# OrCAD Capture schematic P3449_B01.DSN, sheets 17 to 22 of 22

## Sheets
17 0005_SODIMM connector 2_3: size Custom
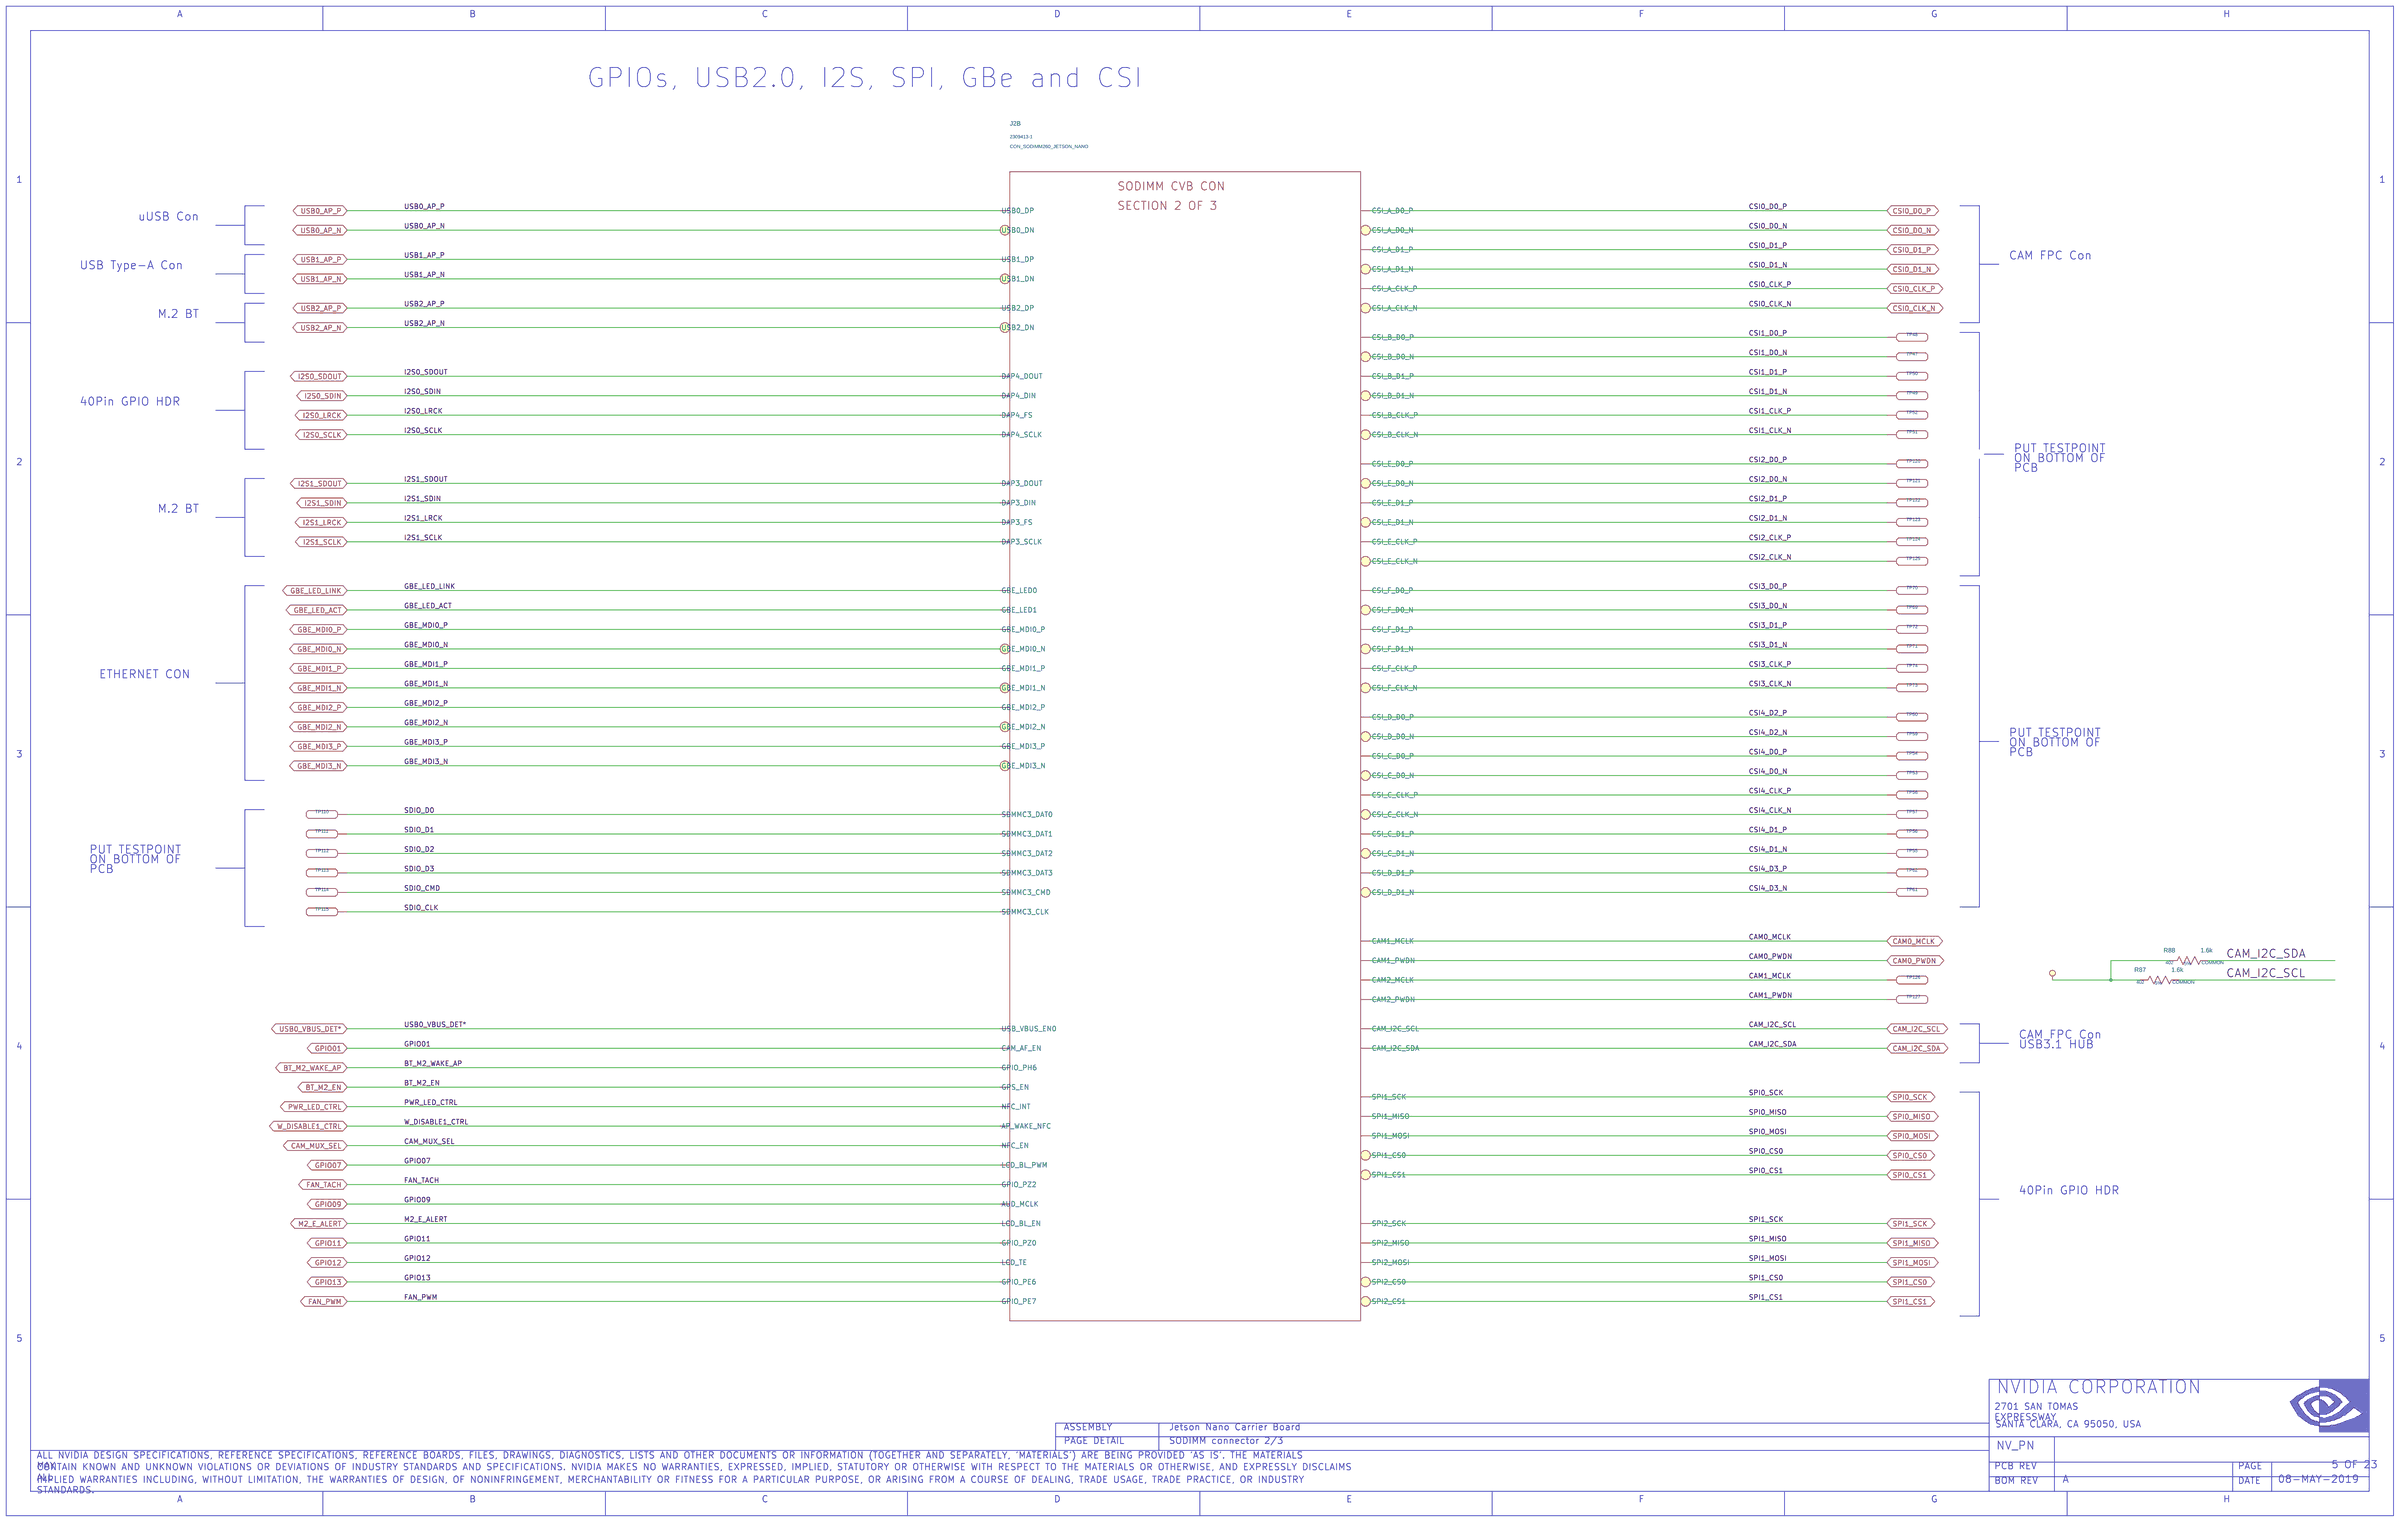
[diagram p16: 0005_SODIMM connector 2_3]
18 0004_SODIMM connector 1_3: size Custom
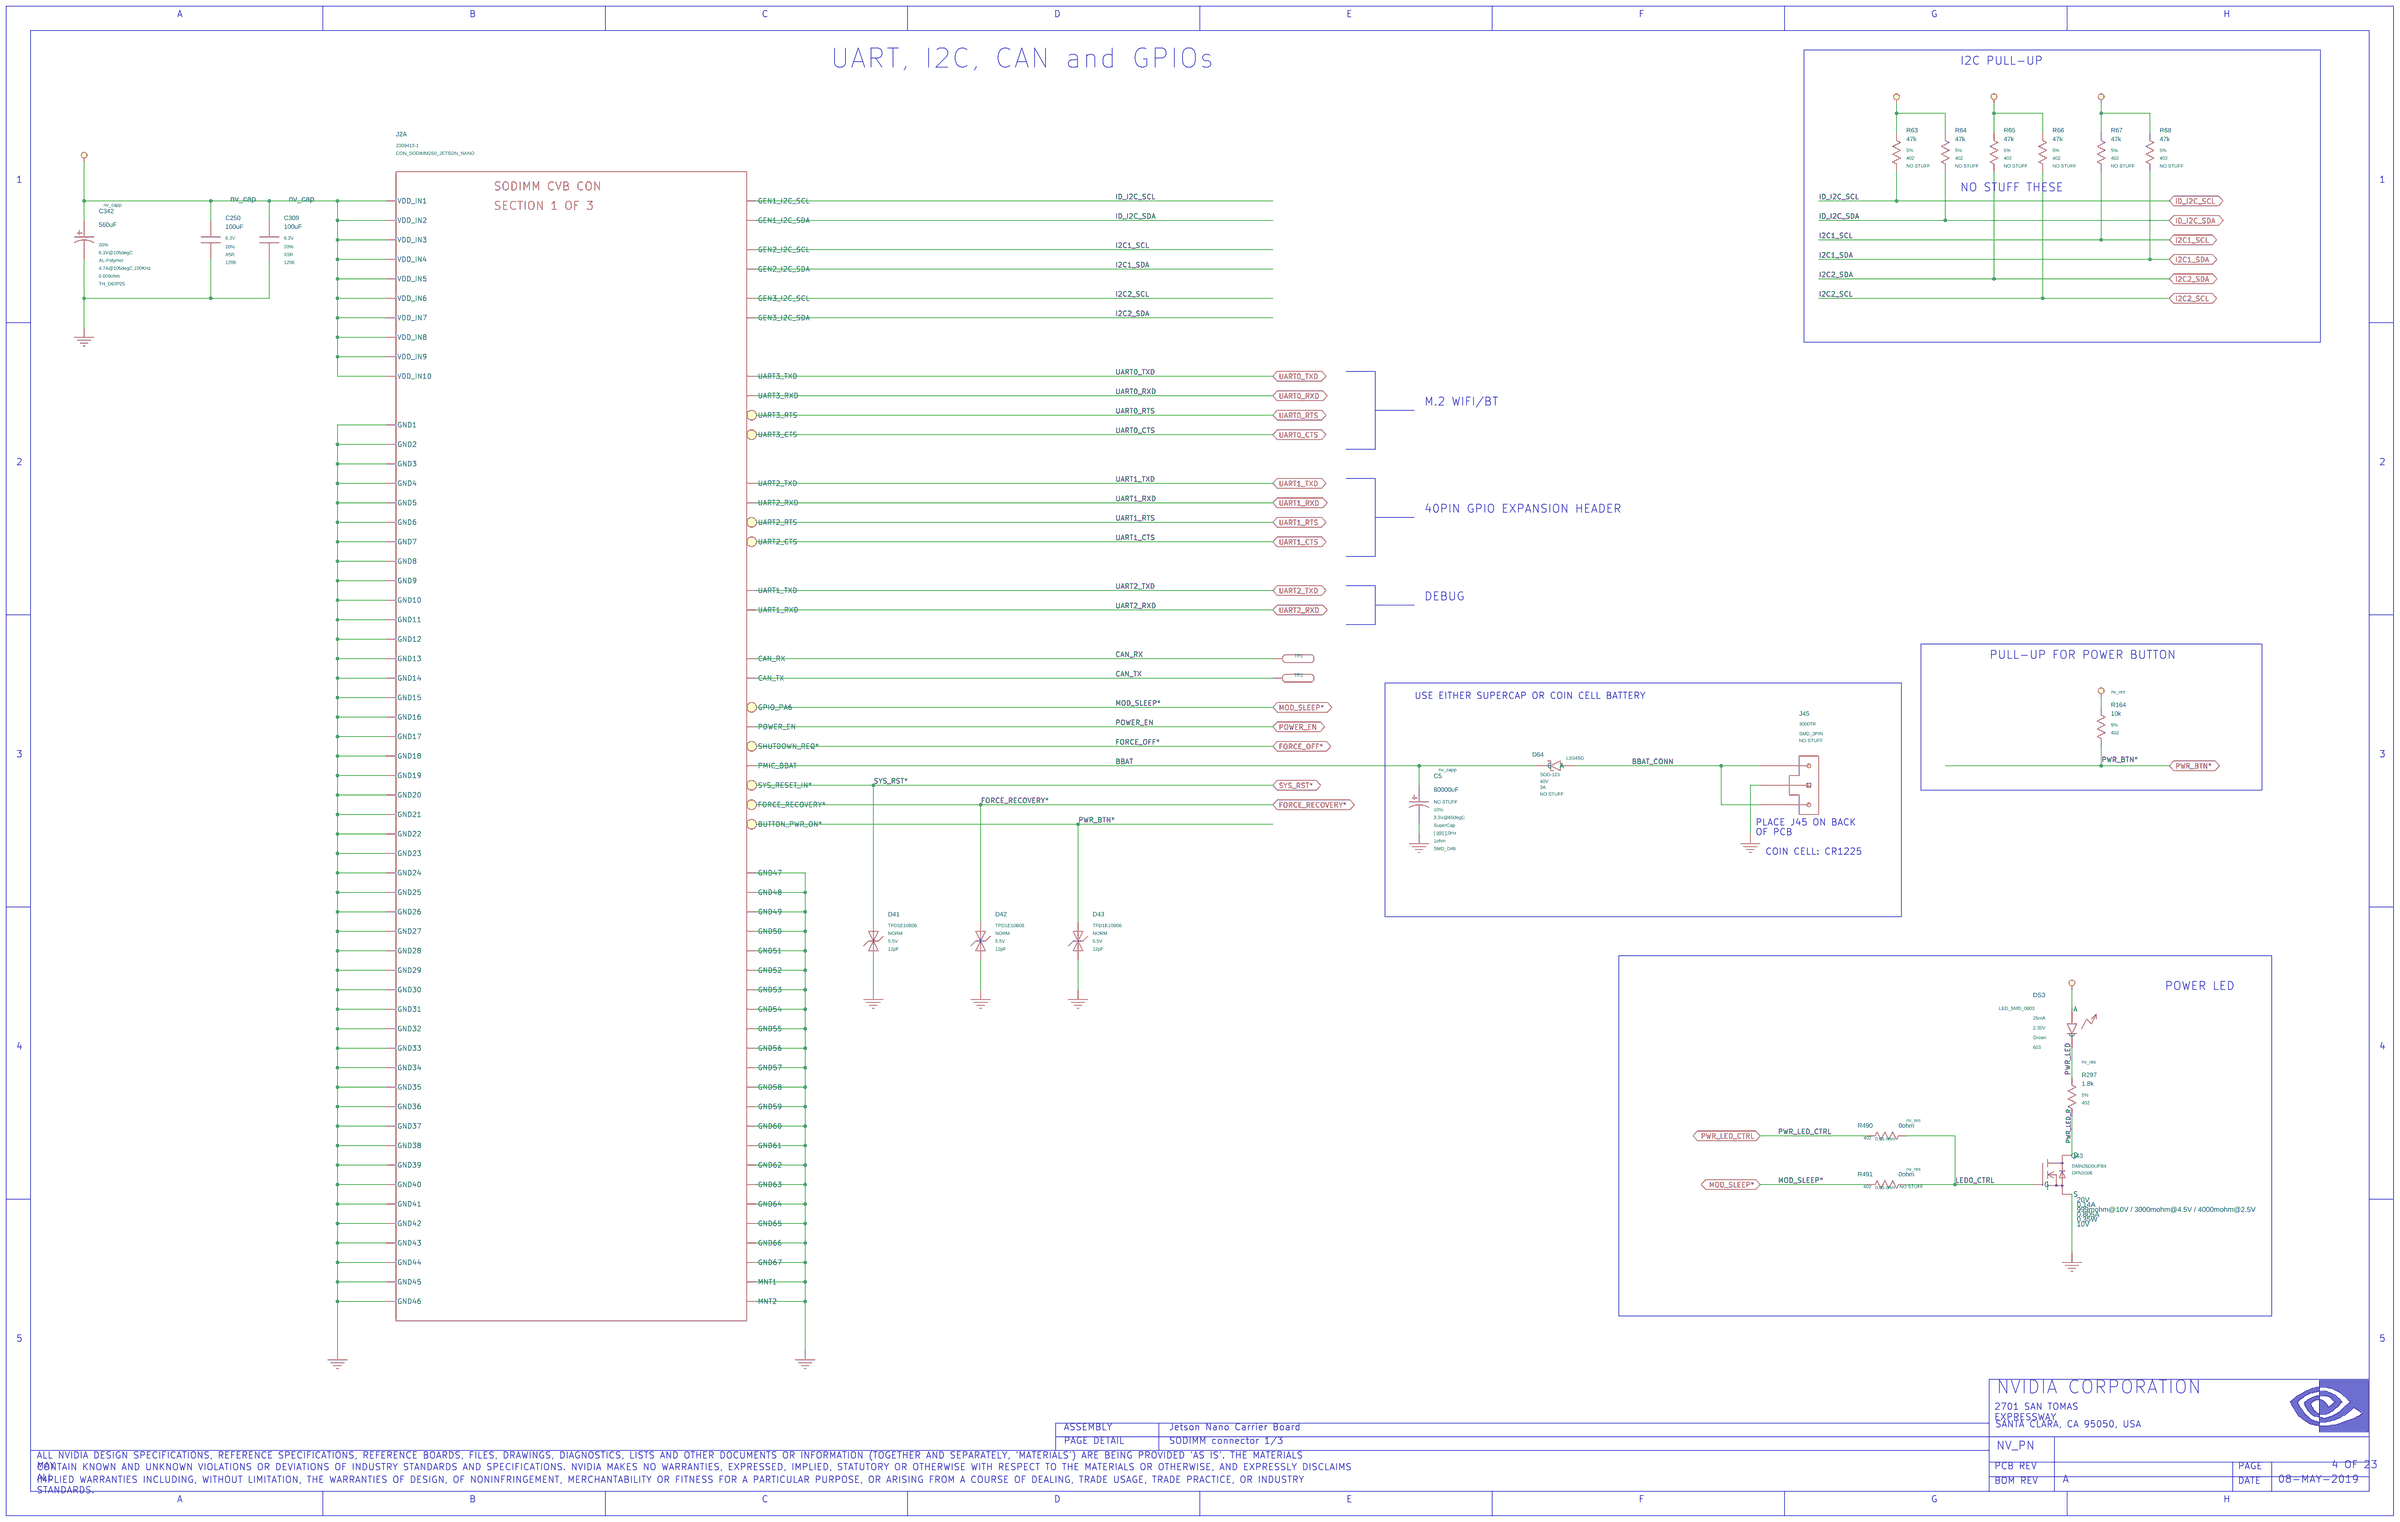
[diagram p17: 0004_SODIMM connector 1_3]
19 0003_Power Tree
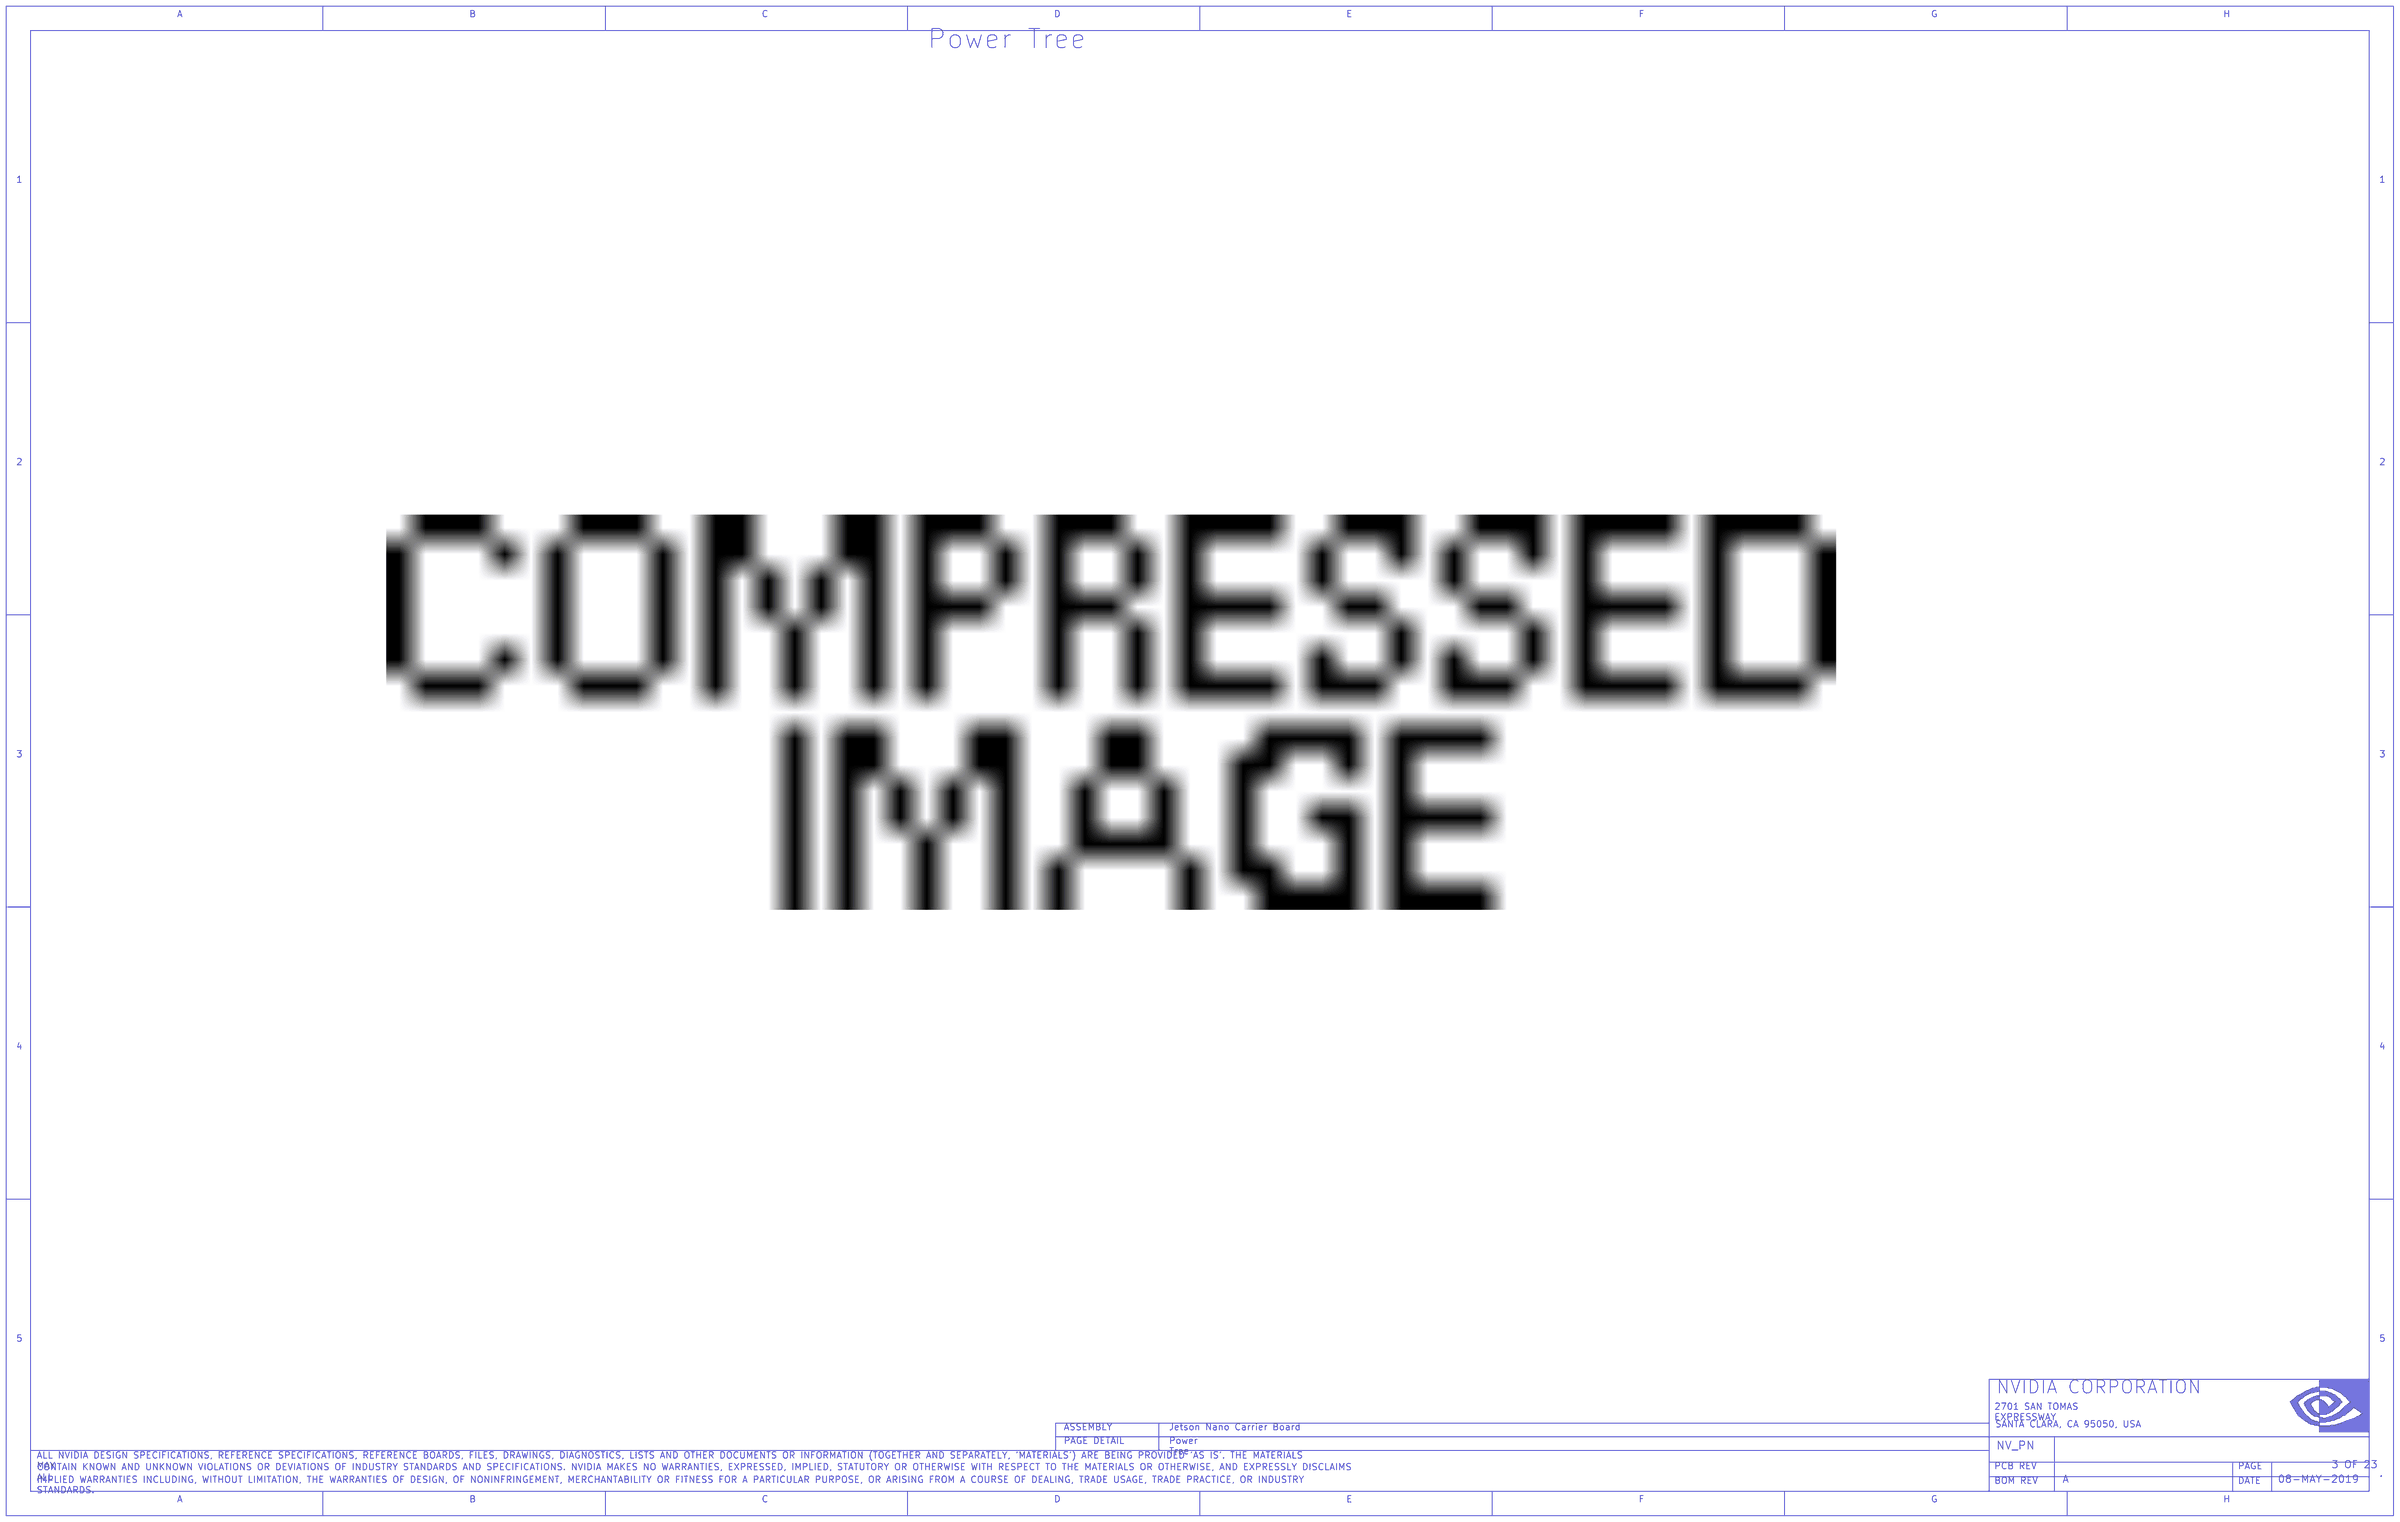
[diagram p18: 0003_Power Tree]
20 0002_Blank Page
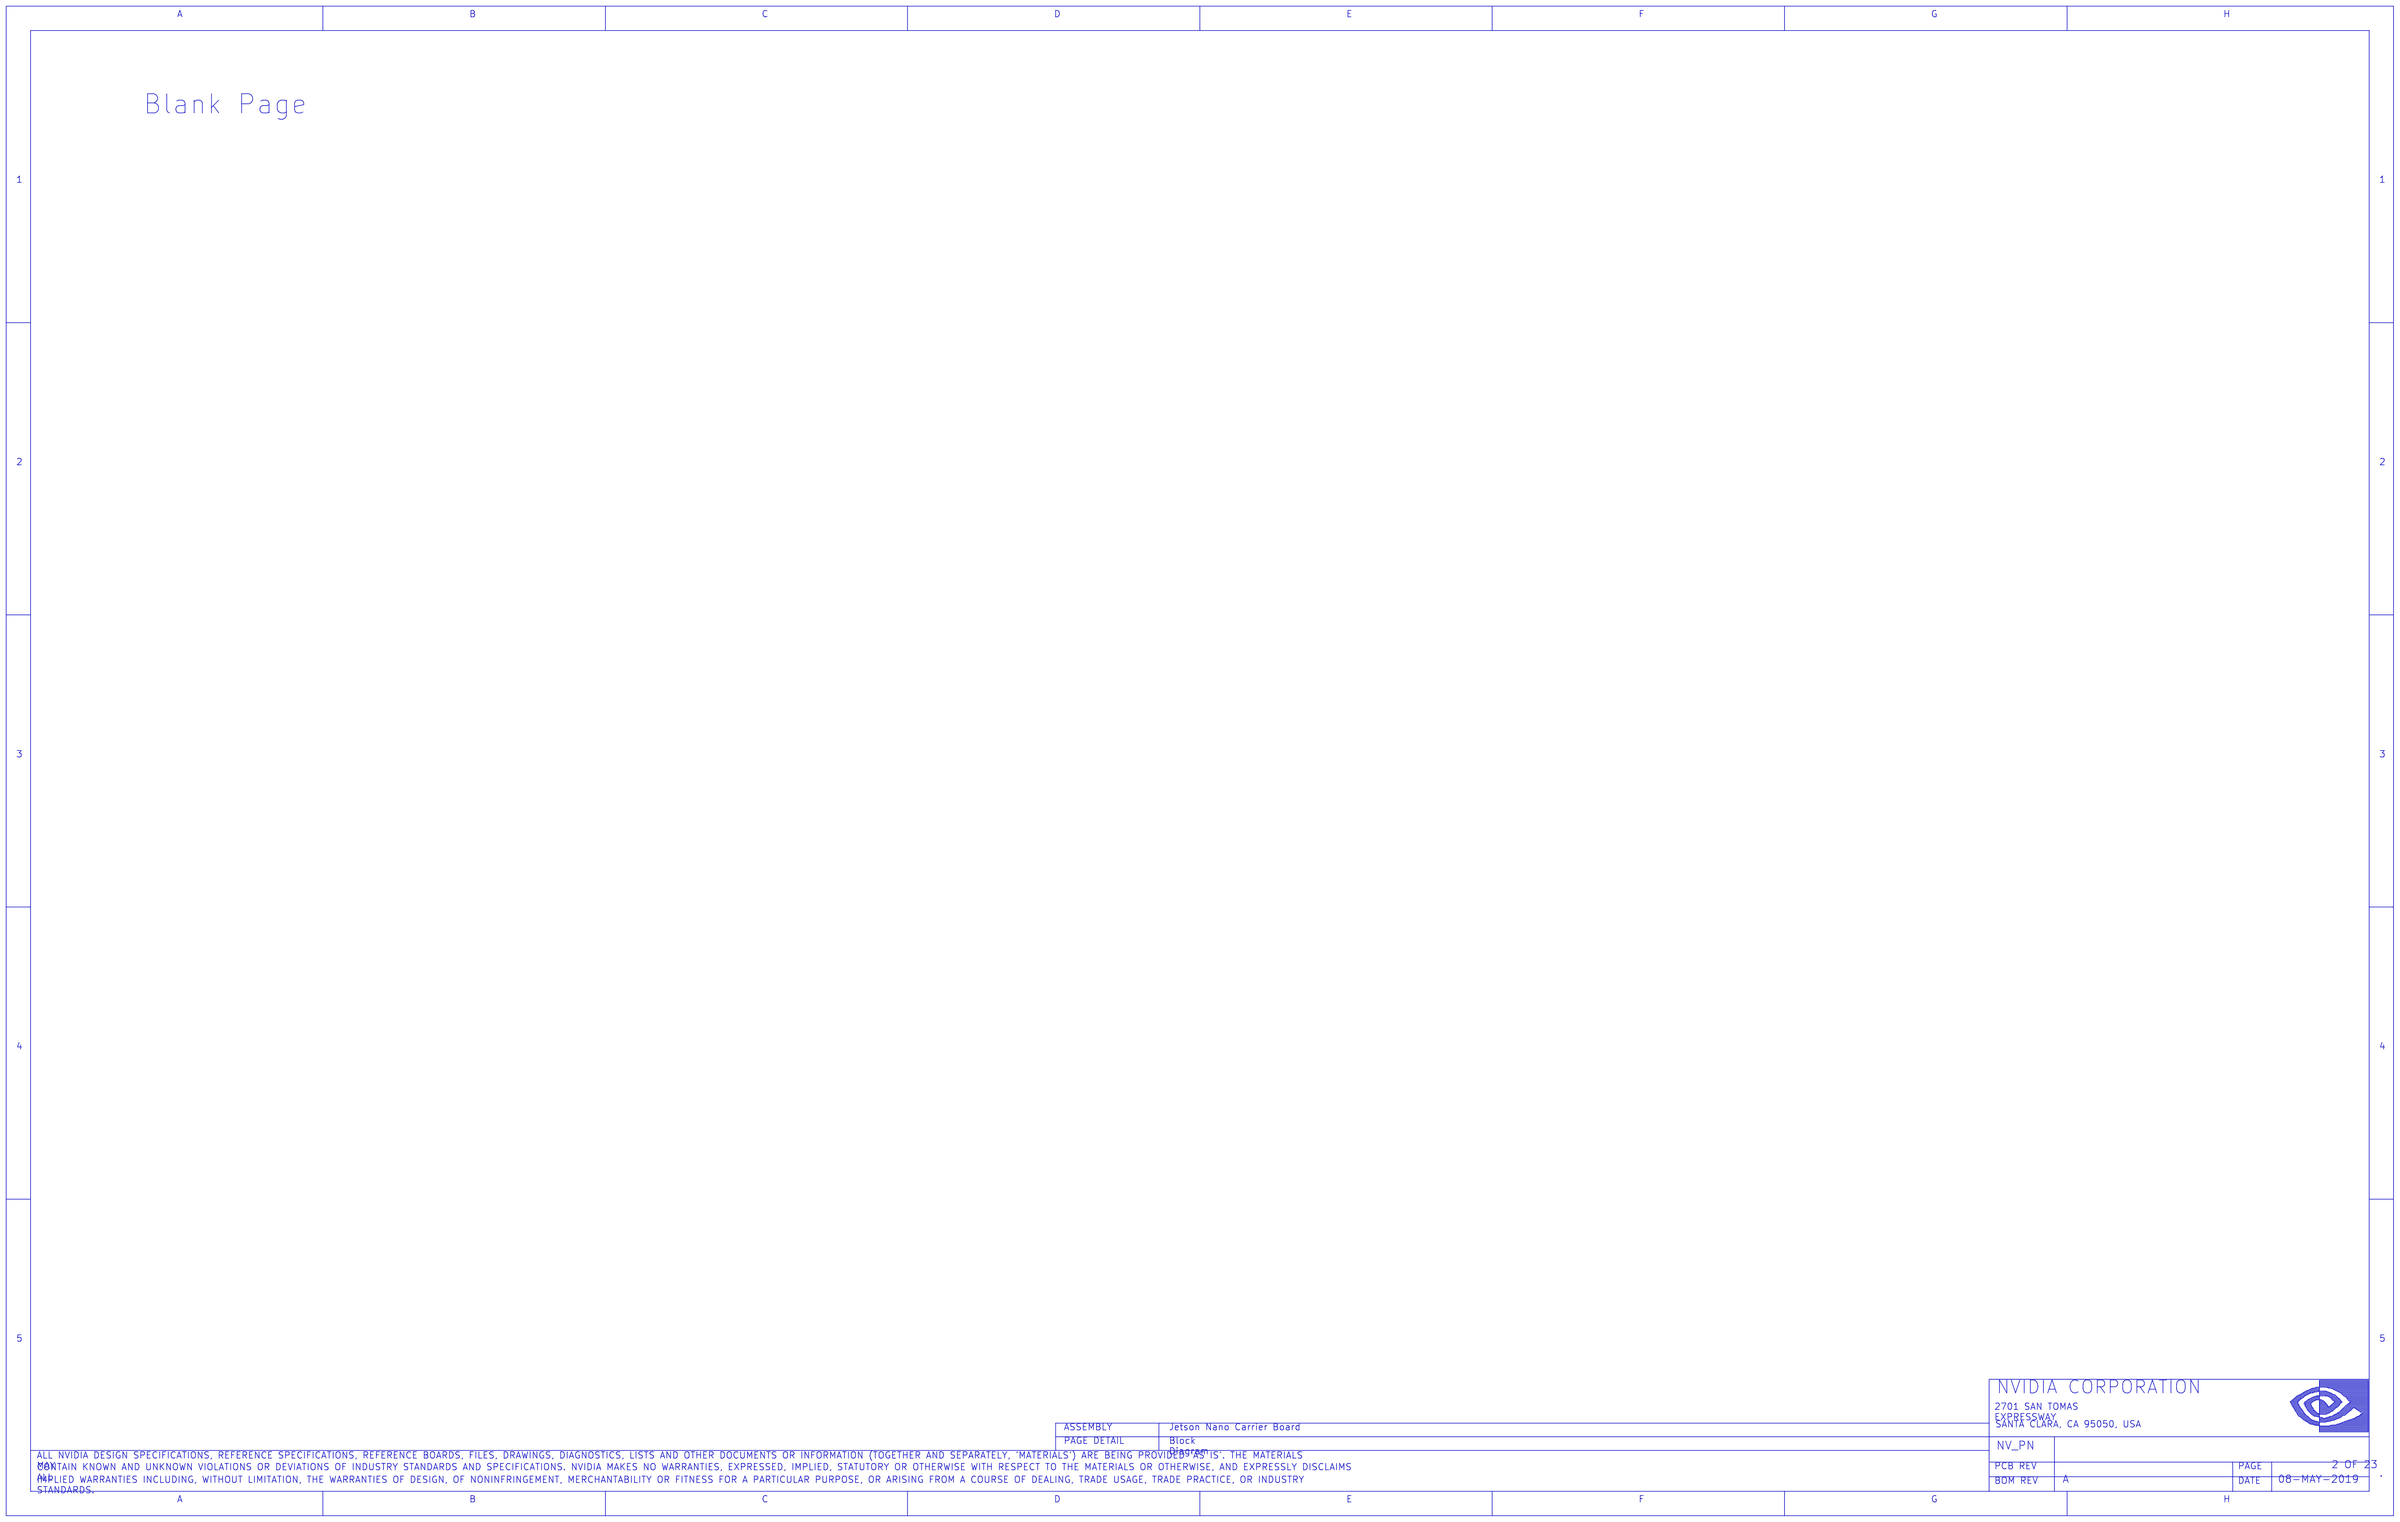
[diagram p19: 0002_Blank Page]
21 0001_Table of Contents
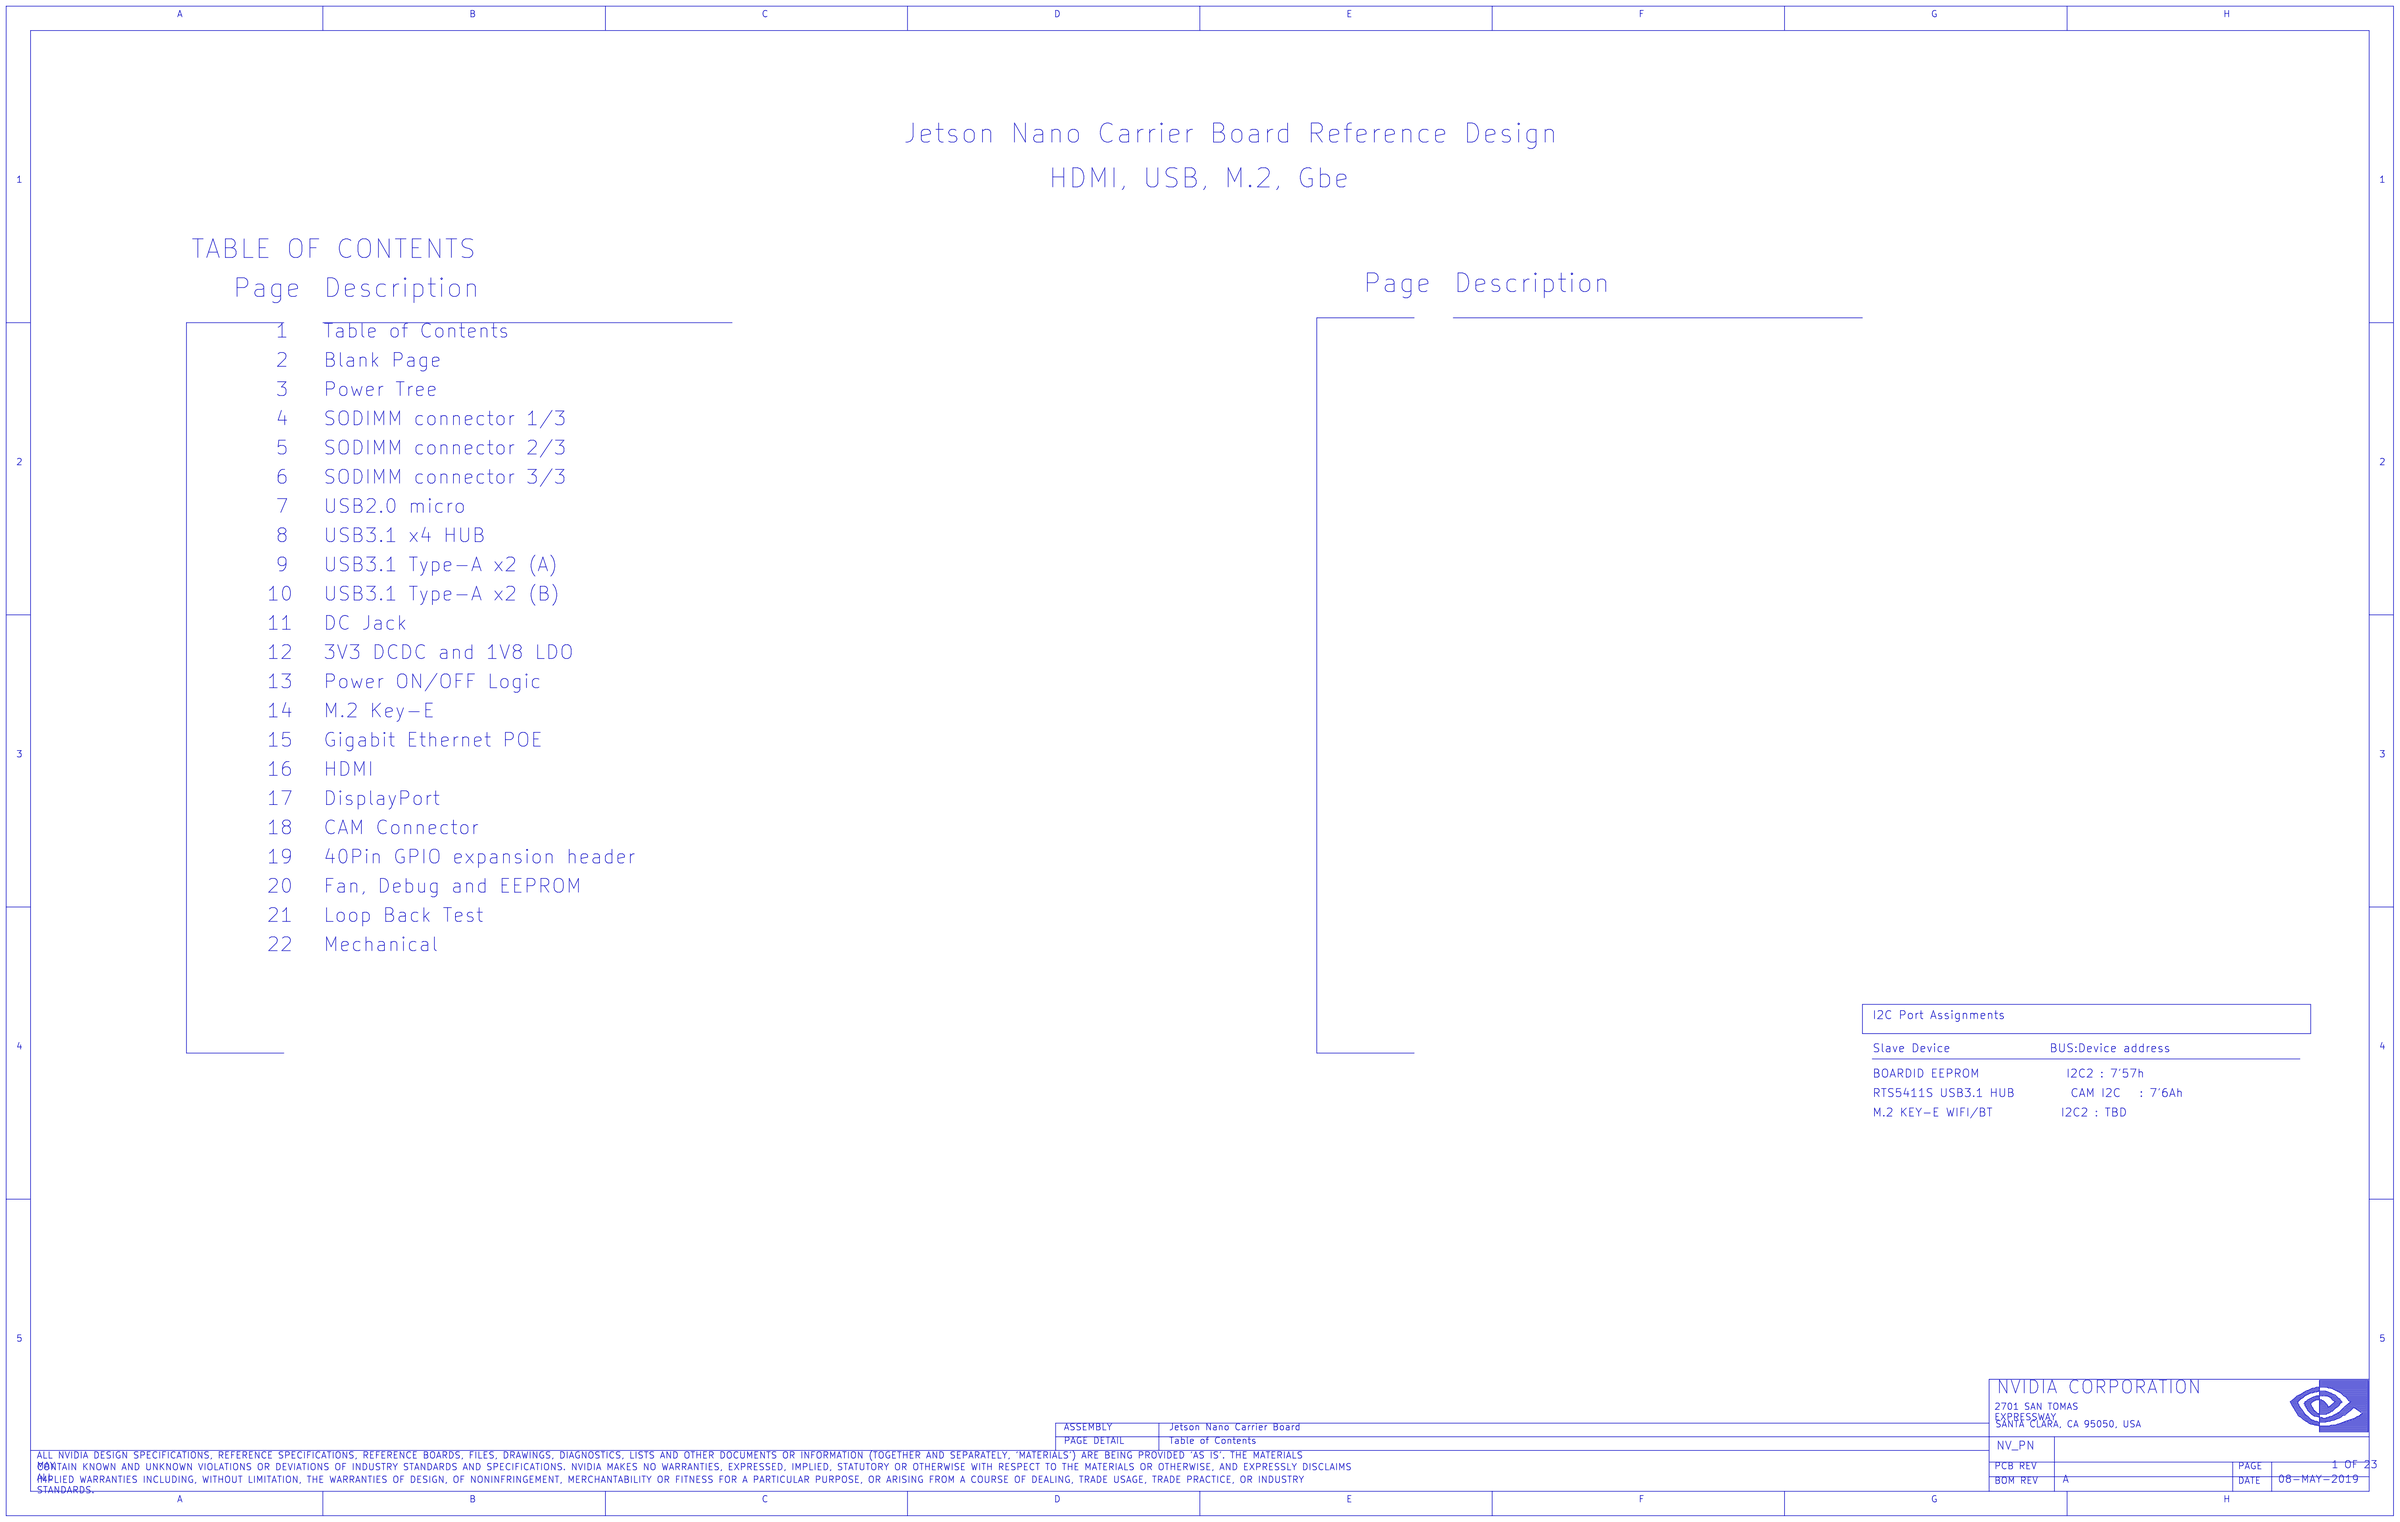
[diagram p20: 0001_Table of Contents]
22 0022_Mechanical: size Custom
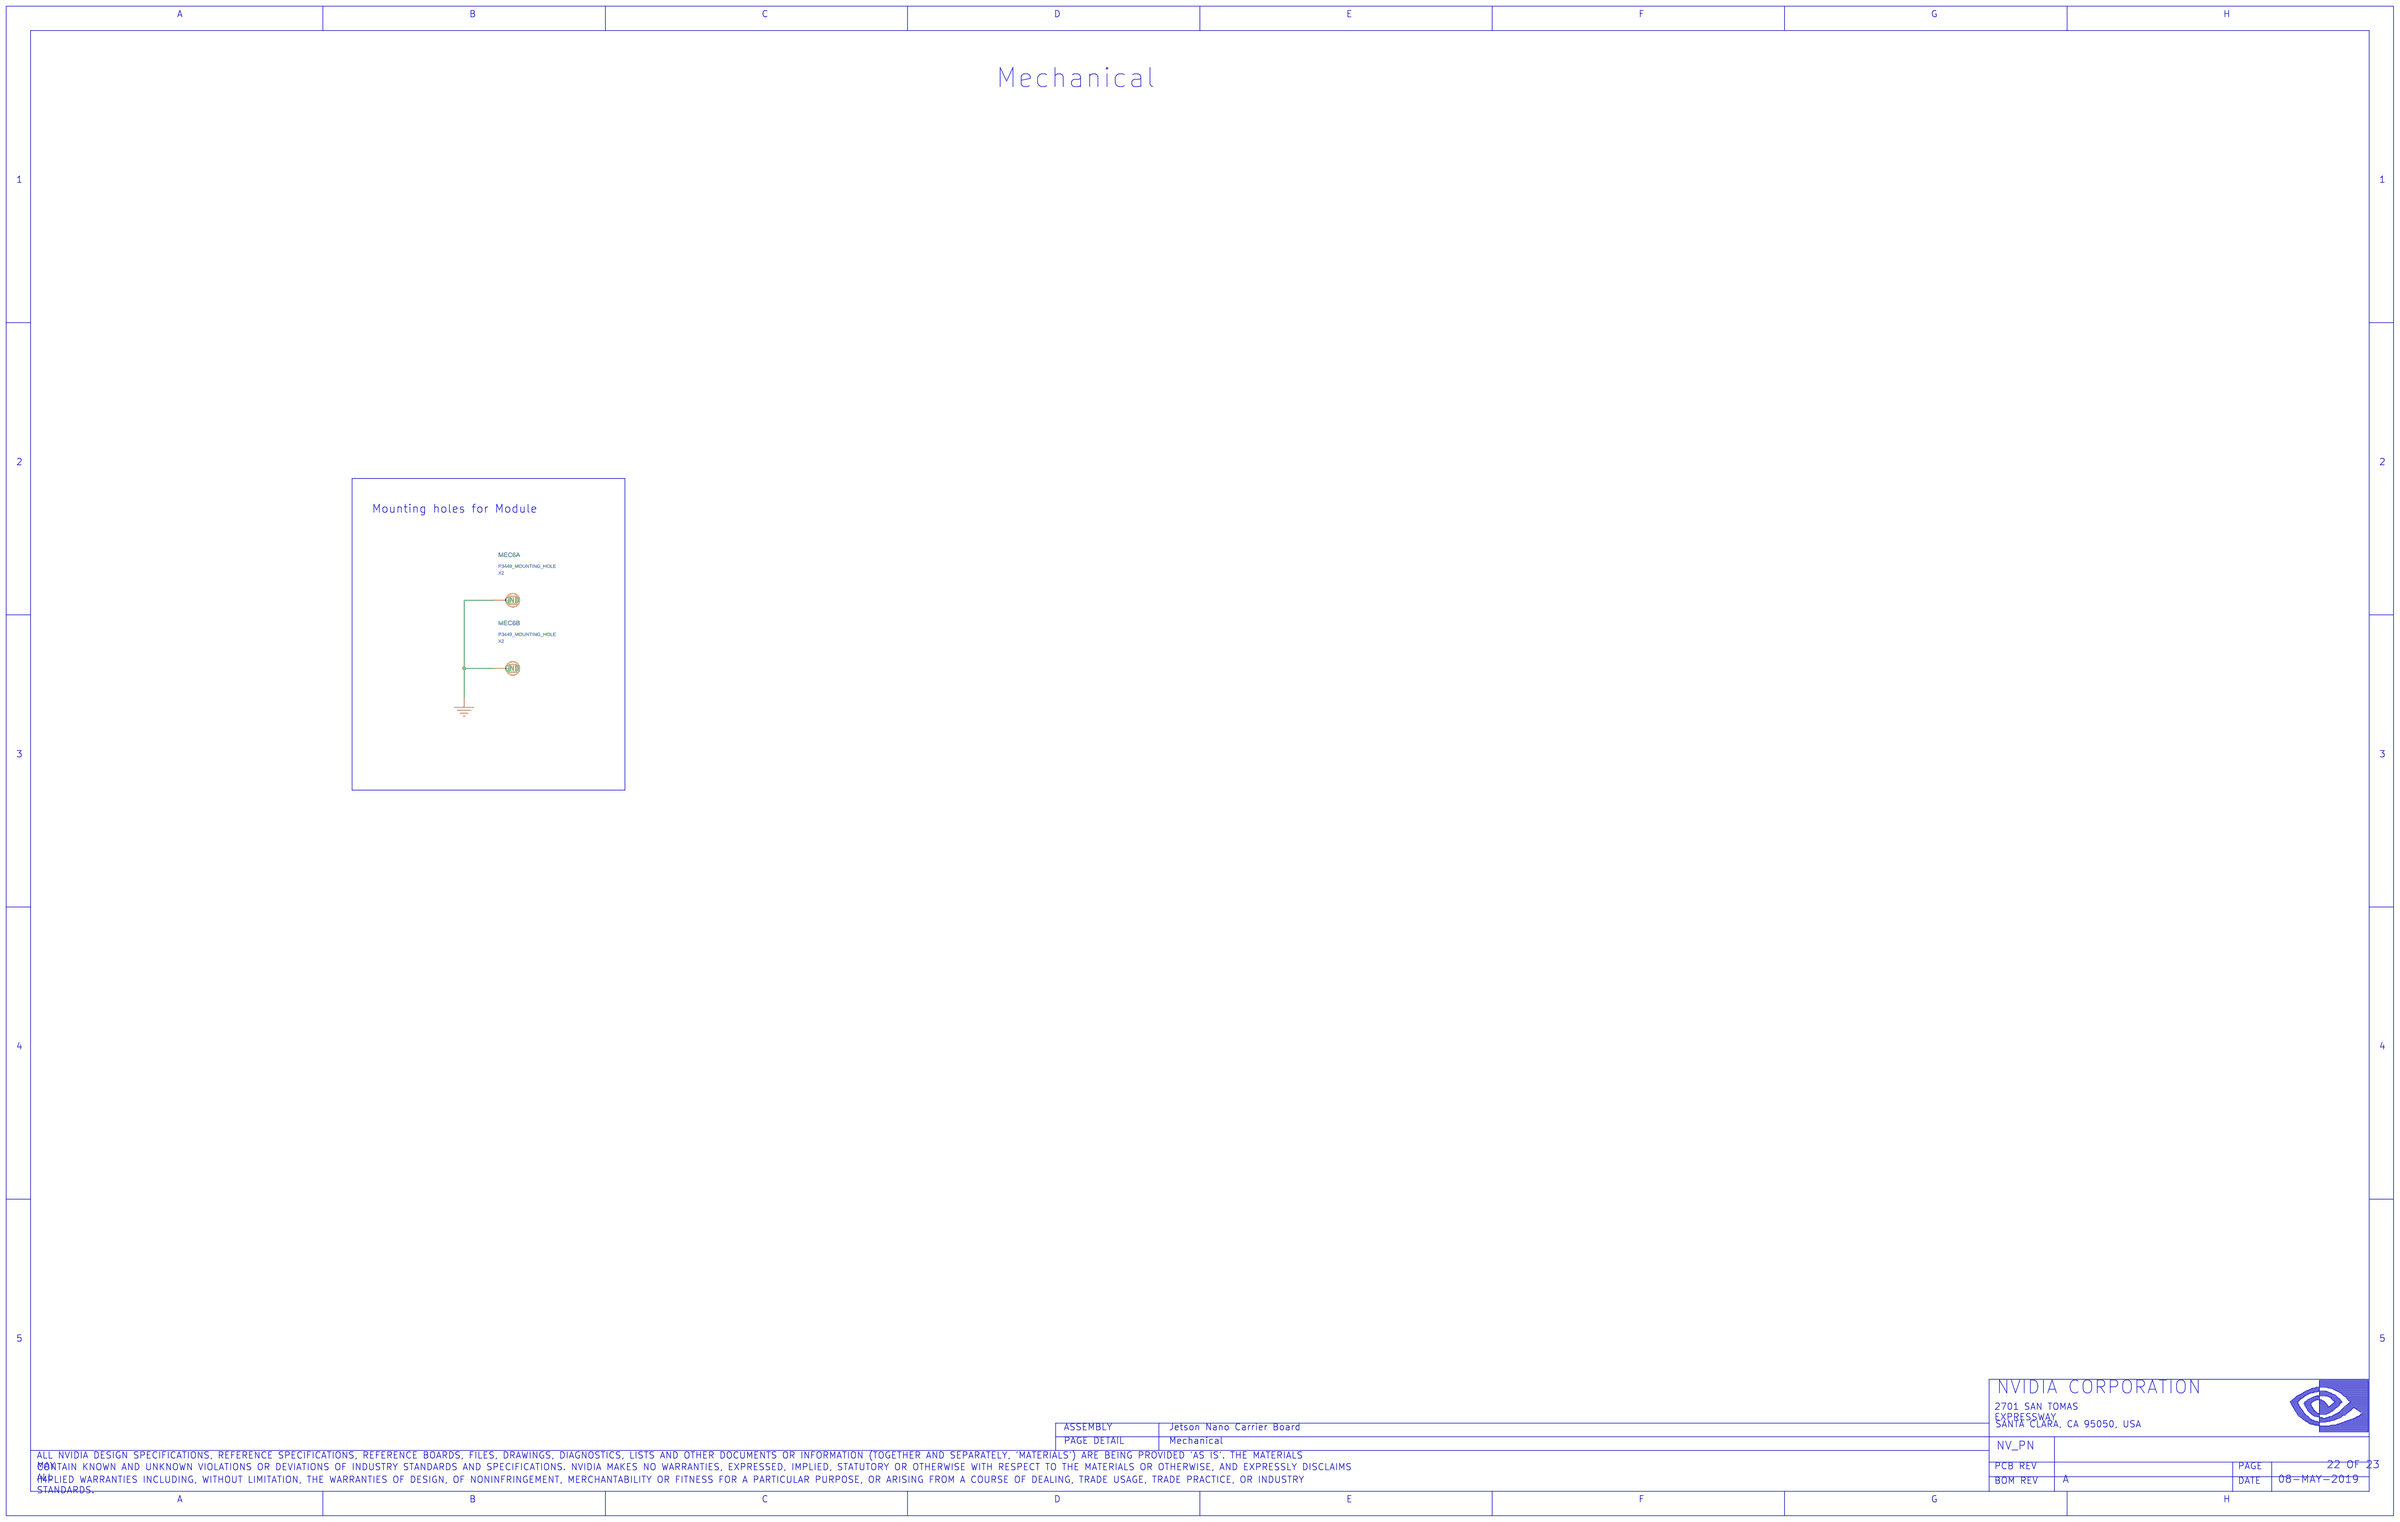
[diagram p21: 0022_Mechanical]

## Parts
sheet 0004_SODIMM connector 1_3
C5  80000uF  [CAP_SMD_048X048]
C250  100uF  [1206]
C309  100uF  [1206]
C342  560uF  [CAP_TH_D063P025]
D41  D_ESD  [DIODE_SMD_010X060]
D42  D_ESD  [DIODE_SMD_010X060]
D43  D_ESD  [DIODE_SMD_010X060]
D64  D_SCHOTTKY  [DIODE_SMD_SOD123]
DS3  LED  [LED_SMD_0603_ST]
J45  CON_BATTERY  [CON_BATTERY_003_SMD_ST_F_132X121]
Q43  Q_FET_N_ENH  [DFET_003_SMD_010X006_B]
R63  47k  [402]
R64  47k  [402]
R65  47k  [402]
R66  47k  [402]
R67  47k  [402]
R68  47k  [402]
R164  10k  [402]
R297  1.8k  [402]
R490  0ohm  [402]
R491  0ohm  [402]
TP1  LABTESTPOINT  [LTPB071C125D045C025P]
TP2  LABTESTPOINT  [LTPB071C125D045C025P]
sheet 0005_SODIMM connector 2_3
R87  1.6k  [402]
R88  1.6k  [402]
TP47  LABTESTPOINT  [LTPB071C125D045C025P]
TP48  LABTESTPOINT  [LTPB071C125D045C025P]
TP49  LABTESTPOINT  [LTPB071C125D045C025P]
TP50  LABTESTPOINT  [LTPB071C125D045C025P]
TP51  LABTESTPOINT  [LTPB071C125D045C025P]
TP52  LABTESTPOINT  [LTPB071C125D045C025P]
TP53  LABTESTPOINT  [LTPB071C125D045C025P]
TP54  LABTESTPOINT  [LTPB071C125D045C025P]
TP55  LABTESTPOINT  [LTPB071C125D045C025P]
TP56  LABTESTPOINT  [LTPB071C125D045C025P]
TP57  LABTESTPOINT  [LTPB071C125D045C025P]
TP58  LABTESTPOINT  [LTPB071C125D045C025P]
TP59  LABTESTPOINT  [LTPB071C125D045C025P]
TP60  LABTESTPOINT  [LTPB071C125D045C025P]
TP61  LABTESTPOINT  [LTPB071C125D045C025P]
TP62  LABTESTPOINT  [LTPB071C125D045C025P]
TP69  LABTESTPOINT  [LTPB071C125D045C025P]
TP70  LABTESTPOINT  [LTPB071C125D045C025P]
TP71  LABTESTPOINT  [LTPB071C125D045C025P]
TP72  LABTESTPOINT  [LTPB071C125D045C025P]
TP73  LABTESTPOINT  [LTPB071C125D045C025P]
TP74  LABTESTPOINT  [LTPB071C125D045C025P]
TP110  LABTESTPOINT  [LTPB071C125D045C025P]
TP111  LABTESTPOINT  [LTPB071C125D045C025P]
TP112  LABTESTPOINT  [LTPB071C125D045C025P]
TP113  LABTESTPOINT  [LTPB071C125D045C025P]
TP114  LABTESTPOINT  [LTPB071C125D045C025P]
TP115  LABTESTPOINT  [LTPB071C125D045C025P]
TP120  LABTESTPOINT  [LTPB071C125D045C025P]
TP121  LABTESTPOINT  [LTPB071C125D045C025P]
TP122  LABTESTPOINT  [LTPB071C125D045C025P]
TP123  LABTESTPOINT  [LTPB071C125D045C025P]
TP124  LABTESTPOINT  [LTPB071C125D045C025P]
TP125  LABTESTPOINT  [LTPB071C125D045C025P]
TP126  LABTESTPOINT  [LTPB071C125D045C025P]
TP127  LABTESTPOINT  [LTPB071C125D045C025P]
sheet 0006_SODIMM connector 3_3
J2  CON_SODIMM_260  [CON_SODIMM_260_SMT_RA_F_P005]  (sections A,B,C)
sheet 0022_Mechanical
MEC6  MOUNTING_HOLE  [MECH_RECT_01000X00790_HOLES]  (sections A,B)

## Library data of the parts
C5 = C_POL: ASSEMBLY: CVB_CONN; CDS_LIB: discrete; CDS_PART_NAME: C_POL_SMD_D48-80000UF,SUPERCAP,10%,3.3V@60DEGC,1OHM,9.999UH,[ ]@[ ],0HZ,060-0002-000; CDS_PHYS_PART_NAME: C_POL_SMD_D48-80000UF,SUPERCAP,10%,3.3V@60DEGC,1OHM,9.999UH,[ ]@[ ],0HZ,060-0002-000-060-0002-000,80000UF; CDS_SEC: 1; DEVICE_TYPENAME: C_POL_SMD_D48-80000UFSUPERCAP1033V60DEGC1OHM9999UH0HZ060-0002-000-060-0002-00080000UF; DRAWING: @P3449_B01_LIB.P3449_B01(SCH_1):PAGE4; ESL: 9.999uH; ESR: 1ohm; MAT: SuperCap; MAX_VOLTAGE: 3.3V@60degC; NV_PN: 060-0002-000; PACK_TYPE: SMD_D48; PATH: I165; PHYS_PAGE: 4; RIPPLE_CURRENT: [ ]@[ ],0Hz; ROT: 0; SEC: 1; SIGNAL_MODEL: nv_capp; SKU: NO STUFF; TOL: 10%; VER: 1; XY: (-4900,3500)
C250 = C#1: ASSEMBLY: CVB_CONN; CDS_LIB: discrete; CDS_PART_NAME: C_1206-100UF,X5R,20%,6.3V,039-0148-000; CDS_PHYS_PART_NAME: C_1206-100UF,X5R,20%,6.3V,039-0148-000-039-0148-000,100UF; CDS_SEC: 1; CHIPS_PART_NAME: C; DEVICE_TYPENAME: C_1206-100UFX5R2063V039-0148-000-039-0148-000100UF; DRAWING: @P3449_B01_LIB.P3449_B01(SCH_1):PAGE4; MAT: X5R; MAX_VOLTAGE: 6.3V; NV_PN: 039-0148-000; PATH: I99; PHYS_PAGE: 4; ROT: 0; SEC: 1; SIGNAL_MODEL: nv_cap; TOL: 20%; VER: 1; XY: (-11100,6400)
C309 = C#1: ASSEMBLY: CVB_CONN; CDS_LIB: discrete; CDS_PART_NAME: C_1206-100UF,X5R,20%,6.3V,039-0148-000; CDS_PHYS_PART_NAME: C_1206-100UF,X5R,20%,6.3V,039-0148-000-039-0148-000,100UF; CDS_SEC: 1; CHIPS_PART_NAME: C; DEVICE_TYPENAME: C_1206-100UFX5R2063V039-0148-000-039-0148-000100UF; DRAWING: @P3449_B01_LIB.P3449_B01(SCH_1):PAGE4; MAT: X5R; MAX_VOLTAGE: 6.3V; NV_PN: 039-0148-000; PATH: I100; PHYS_PAGE: 4; ROT: 0; SEC: 1; SIGNAL_MODEL: nv_cap; TOL: 20%; VER: 1; XY: (-10800,6400)
C342 = C_POL: ASSEMBLY: CVB_CONN; CDS_LIB: discrete; CDS_PART_NAME: C_POL_TH_D63P25-560UF,AL-POLYMER,20%,6.3V@105DEGC,0.008OHM,0.999UH,4.7A@105DEGC,100KHZ,032-1441-000; CDS_PHYS_PART_NAME: C_POL_TH_D63P25-560UF,AL-POLYMER,20%,6.3V@105DEGC,0.008OHM,0.999UH,4.7A@105DEGC,100KHZ,032-1441-000-032-1441-000,560UF; CDS_SEC: 1; DEVICE_TYPENAME: C_POL_TH_D63P25-560UFAL-POLYMER2063V105DEGC0008OHM0999UH47A105DEGC100KHZ032-1441-000-032-1441-000560UF; DRAWING: @P3449_B01_LIB.P3449_B01(SCH_1):PAGE4; ESL: 0.999uH; ESR: 0.008ohm; MAT: AL-Polymer; MAX_VOLTAGE: 6.3V@105degC; NV_PN: 032-1441-000; PACK_TYPE: TH_D63P25; PATH: I179; PHYS_PAGE: 4; PLACEMENT_NOTE: Place close to J32 and J33; RIPPLE_CURRENT: 4.7A@105degC,100KHz; ROT: 0; SEC: 1; SIGNAL_MODEL: nv_capp; TOL: 20%; VER: 1; XY: (-11750,6400)
D41 = D_ESD: ASSEMBLY: CVB_CONN; BREAKDOWN_VOLTAGE_MIN_TYP: 6V; CAPACITANCE_MAX_TYP: 12pF; CDS_LIB: discrete; CDS_PART_NAME: D_ESD_NORM-TPD1E10B06,1 LINE,BI-DIRECTIONAL,5.5V,0.1UA,6V,10V@1A,12PF,090-0243-000; CDS_PHYS_PART_NAME: D_ESD_NORM-TPD1E10B06,1 LINE,BI-DIRECTIONAL,5.5V,0.1UA,6V,10V@1A,12PF,090-0243-000-090-0243-000; CDS_SEC: 1; CLAMPING_VOLTAGE: 10V@1A; CONFIGURATION: 1 Line; DEVICE_TYPENAME: D_ESD_NORM-TPD1E10B061LINEBI-DIRECTIONAL55V01UA6V10V1A12PF090-0243-000-090-0243-000; DRAWING: @P3449_B01_LIB.P3449_B01(SCH_1):PAGE4; MAX_REVERSE_LEAKAGE_CURRENT: 0.1uA; MAX_REVERSE_VOLTAGE: 5.5V; NV_NAME: TPD1E10B06; NV_PN: 090-0243-000; PACK_TYPE: NORM; PATH: I173; PHYS_PAGE: 4; POLARITY: Bi-Directional; ROT: 0; SEC: 1; VER: 2; XY: (-7700,2800)
D42 = D_ESD: ASSEMBLY: CVB_CONN; BREAKDOWN_VOLTAGE_MIN_TYP: 6V; CAPACITANCE_MAX_TYP: 12pF; CDS_LIB: discrete; CDS_PART_NAME: D_ESD_NORM-TPD1E10B06,1 LINE,BI-DIRECTIONAL,5.5V,0.1UA,6V,10V@1A,12PF,090-0243-000; CDS_PHYS_PART_NAME: D_ESD_NORM-TPD1E10B06,1 LINE,BI-DIRECTIONAL,5.5V,0.1UA,6V,10V@1A,12PF,090-0243-000-090-0243-000; CDS_SEC: 1; CLAMPING_VOLTAGE: 10V@1A; CONFIGURATION: 1 Line; DEVICE_TYPENAME: D_ESD_NORM-TPD1E10B061LINEBI-DIRECTIONAL55V01UA6V10V1A12PF090-0243-000-090-0243-000; DRAWING: @P3449_B01_LIB.P3449_B01(SCH_1):PAGE4; MAX_REVERSE_LEAKAGE_CURRENT: 0.1uA; MAX_REVERSE_VOLTAGE: 5.5V; NV_NAME: TPD1E10B06; NV_PN: 090-0243-000; PACK_TYPE: NORM; PATH: I171; PHYS_PAGE: 4; POLARITY: Bi-Directional; ROT: 0; SEC: 1; VER: 2; XY: (-7150,2800)
D43 = D_ESD: ASSEMBLY: CVB_CONN; BREAKDOWN_VOLTAGE_MIN_TYP: 6V; CAPACITANCE_MAX_TYP: 12pF; CDS_LIB: discrete; CDS_PART_NAME: D_ESD_NORM-TPD1E10B06,1 LINE,BI-DIRECTIONAL,5.5V,0.1UA,6V,10V@1A,12PF,090-0243-000; CDS_PHYS_PART_NAME: D_ESD_NORM-TPD1E10B06,1 LINE,BI-DIRECTIONAL,5.5V,0.1UA,6V,10V@1A,12PF,090-0243-000-090-0243-000; CDS_SEC: 1; CLAMPING_VOLTAGE: 10V@1A; CONFIGURATION: 1 Line; DEVICE_TYPENAME: D_ESD_NORM-TPD1E10B061LINEBI-DIRECTIONAL55V01UA6V10V1A12PF090-0243-000-090-0243-000; DRAWING: @P3449_B01_LIB.P3449_B01(SCH_1):PAGE4; MAX_REVERSE_LEAKAGE_CURRENT: 0.1uA; MAX_REVERSE_VOLTAGE: 5.5V; NV_NAME: TPD1E10B06; NV_PN: 090-0243-000; PACK_TYPE: NORM; PATH: I169; PHYS_PAGE: 4; POLARITY: Bi-Directional; ROT: 0; SEC: 1; VER: 2; XY: (-6650,2800)
D64 = D_SCHOTTKY: ASSEMBLY: CVB_CONN; CDS_LIB: discrete; CDS_PART_NAME: D_SCHOTTKY_SOD-123-LS34SG,SINGLE,40V,25A,0.38V@1A,3A,090-0155-000; CDS_PHYS_PART_NAME: D_SCHOTTKY_SOD-123-LS34SG,SINGLE,40V,25A,0.38V@1A,3A,090-0155-000-090-0155-000; CDS_SEC: 1; CONFIGURATION: Single; CONTINUOUS_CURRENT: 3A; DEVICE_TYPENAME: D_SCHOTTKY_SOD-123-LS34SGSINGLE40V25A038V1A3A090-0155-000-090-0155-000; DRAWING: @P3449_B01_LIB.P3449_B01(SCH_1):PAGE4; FORWARD_VOLTAGE: 0.38V@1A; MAX_CURRENT: 25A; MAX_VOLTAGE: 40V; NV_NAME: LS34SG; NV_PN: 090-0155-000; PACK_TYPE: SOD-123; PATH: I175; PHYS_PAGE: 4; PLACEMENT_NOTE: bottom side of pcb near J45; ROT: 0; SEC: 1; SKU: NO STUFF; VER: 1; XY: (-4200,3700)
DS3 = LED: ASSEMBLY: POWER_LED; CDS_LIB: discrete; CDS_PART_NAME: LED_0603-LED_SMD_0603,5V,60MA,2.35V,25MA,GREEN,092-0073-000; CDS_PHYS_PART_NAME: LED_0603-LED_SMD_0603,5V,60MA,2.35V,25MA,GREEN,092-0073-000-092-0073-000; CDS_SEC: 1; CONTINUOUS_CURRENT: 25mA; DEVICE_TYPENAME: LED_0603-LED_SMD_06035V60MA235V25MAGREEN092-0073-000-092-0073-000; DRAWING: @P3449_B01_LIB.P3449_B01(SCH_1):PAGE4; FORWARD_VOLTAGE: 2.35V; MAX_CURRENT: 60mA; MAX_VOLTAGE: 5V; NV_COLOR: Green; NV_NAME: LED_SMD_0603; NV_PN: 092-0073-000; PACK_TYPE: 603; PATH: I93; PHYS_PAGE: 4; ROT: 0; SEC: 1; VER: 1; XY: (-1550,2350)
J45 = CON_BATTERY: ANGLE: N/A; ASSEMBLY: CVB_CONN; CDS_LIB: electro_mechanic; CDS_PART_NAME: CON_BATTERY_SMD_3PIN-3000TR,FEMALE,N/A,N/A,YES,NO,NO,NO,YES,N/A,N/A,220-0146-000; CDS_PHYS_PART_NAME: CON_BATTERY_SMD_3PIN-3000TR,FEMALE,N/A,N/A,YES,NO,NO,NO,YES,N/A,N/A,220-0146-000-220-0146-000; CDS_SEC: 1; DEVICE_TYPENAME: CON_BATTERY_SMD_3PIN-3000TRFEMALENANAYESNONONOYESNANA220-0146-000-220-0146-000; DRAWING: @P3449_B01_LIB.P3449_B01(SCH_1):PAGE4; EMI_GROUND_TAB: NO; GENDER: FEMALE; LATCHING: NO; MAX_CURRENT: N/A; MAX_VOLTAGE: N/A; NV_NAME: 3000TR; NV_PN: 220-0146-000; PACK_TYPE: SMD_3PIN; PATH: I162; PHYS_PAGE: 4; PITCH: N/A; REFLOW: YES; ROT: 0; SEC: 1; SHIELDED: YES; SHROUDED: NO; SKU: NO STUFF; VER: 1; XY: (-2900,3600)
Q43 = Q_FET_N_ENH#1: ASSEMBLY: POWER_LED; CDS_LIB: discrete; CDS_PART_NAME: Q_FET_N_ENH_DFN1006-DMN26D0UFB4,20V,999MOHM@10V / 3000MOHM@4.5V / 4000MOHM@2.5V,0.14A,0.805A,10V,0.35W,999NC@10V / 0NC@4.5V / A; CDS_PHYS_PART_NAME: Q_FET_N_ENH_DFN1006-DMN26D0UFB4,20V,999MOHM@10V / 3000MOHM@4.5V / 4000MOHM@2.5V,0.14A,0.805A,10V,0.35W,999NC@10V / 0NC@4.5V / B; CDS_SEC: 1; CONTINUOUS_CURRENT: 0.14A; CaptureCellPackProp: Q_FET_N_ENH##1; DEVICE_TYPENAME: Q_FET_N_ENH_DFN1006-DMN26D0UFB420V999MOHM10V3000MOHM45V4000MOHM25V014A0805A10V035W999NC10V0NC45VB; DRAWING: @P3449_B01_LIB.P3449_B01(SCH_1):PAGE4; MAX_CURRENT: 0.805A; MAX_VOLTAGE: 20V; MAX_WATTAGE: 0.35W; NV_NAME: DMN26D0UFB4; NV_PN: 300-0868-000; PACK_TYPE: DFN1006; PATH: I102; PHYS_PAGE: 4; Q_G: 999nC@10V / 0nC@4.5V / 999nC@2.5V; ROT: 0; R_DS_ON: 999mohm@10V / 3000mohm@4.5V / 4000mohm@2.5V; SEC: 1; VER: 2; V_BE_GS: 10V; XY: (-1650,1600)
R63 = R: ASSEMBLY: CVB_CONN; CDS_LIB: discrete; CDS_PART_NAME: R_0402-47K,5 %,62.5MW,195-0599-000; CDS_PHYS_PART_NAME: R_0402-47K,5 %,62.5MW,195-0599-000-195-0599-000,47K; CDS_SEC: 1; DEVICE_TYPENAME: R_0402-47K5625MW195-0599-000-195-0599-00047K; DRAWING: @P3449_B01_LIB.P3449_B01(SCH_1):PAGE4; MAX_WATTAGE: 62.5mW; NV_PN: 195-0599-000; PATH: I62; PHYS_PAGE: 4; ROT: 0; SEC: 1; SIGNAL_MODEL: nv_res; SKU: NO STUFF; TOL: 5%; VER: 2; XY: (-2450,6850)
R64 = R: ASSEMBLY: CVB_CONN; CDS_LIB: discrete; CDS_PART_NAME: R_0402-47K,5 %,62.5MW,195-0599-000; CDS_PHYS_PART_NAME: R_0402-47K,5 %,62.5MW,195-0599-000-195-0599-000,47K; CDS_SEC: 1; DEVICE_TYPENAME: R_0402-47K5625MW195-0599-000-195-0599-00047K; DRAWING: @P3449_B01_LIB.P3449_B01(SCH_1):PAGE4; MAX_WATTAGE: 62.5mW; NV_PN: 195-0599-000; PATH: I63; PHYS_PAGE: 4; ROT: 0; SEC: 1; SIGNAL_MODEL: nv_res; SKU: NO STUFF; TOL: 5%; VER: 2; XY: (-2200,6850)
R65 = R: ASSEMBLY: CVB_CONN; CDS_LIB: discrete; CDS_PART_NAME: R_0402-47K,5 %,62.5MW,195-0599-000; CDS_PHYS_PART_NAME: R_0402-47K,5 %,62.5MW,195-0599-000-195-0599-000,47K; CDS_SEC: 1; DEVICE_TYPENAME: R_0402-47K5625MW195-0599-000-195-0599-00047K; DRAWING: @P3449_B01_LIB.P3449_B01(SCH_1):PAGE4; MAX_WATTAGE: 62.5mW; NV_PN: 195-0599-000; PATH: I64; PHYS_PAGE: 4; ROT: 0; SEC: 1; SIGNAL_MODEL: nv_res; SKU: NO STUFF; TOL: 5%; VER: 2; XY: (-1950,6850)
R66 = R: ASSEMBLY: CVB_CONN; CDS_LIB: discrete; CDS_PART_NAME: R_0402-47K,5 %,62.5MW,195-0599-000; CDS_PHYS_PART_NAME: R_0402-47K,5 %,62.5MW,195-0599-000-195-0599-000,47K; CDS_SEC: 1; DEVICE_TYPENAME: R_0402-47K5625MW195-0599-000-195-0599-00047K; DRAWING: @P3449_B01_LIB.P3449_B01(SCH_1):PAGE4; MAX_WATTAGE: 62.5mW; NV_PN: 195-0599-000; PATH: I65; PHYS_PAGE: 4; ROT: 0; SEC: 1; SIGNAL_MODEL: nv_res; SKU: NO STUFF; TOL: 5%; VER: 2; XY: (-1700,6850)
R67 = R: ASSEMBLY: CVB_CONN; CDS_LIB: discrete; CDS_PART_NAME: R_0402-47K,5 %,62.5MW,195-0599-000; CDS_PHYS_PART_NAME: R_0402-47K,5 %,62.5MW,195-0599-000-195-0599-000,47K; CDS_SEC: 1; DEVICE_TYPENAME: R_0402-47K5625MW195-0599-000-195-0599-00047K; DRAWING: @P3449_B01_LIB.P3449_B01(SCH_1):PAGE4; MAX_WATTAGE: 62.5mW; NV_PN: 195-0599-000; PATH: I66; PHYS_PAGE: 4; ROT: 0; SEC: 1; SIGNAL_MODEL: nv_res; SKU: NO STUFF; TOL: 5%; VER: 2; XY: (-1400,6850)
R68 = R: ASSEMBLY: CVB_CONN; CDS_LIB: discrete; CDS_PART_NAME: R_0402-47K,5 %,62.5MW,195-0599-000; CDS_PHYS_PART_NAME: R_0402-47K,5 %,62.5MW,195-0599-000-195-0599-000,47K; CDS_SEC: 1; DEVICE_TYPENAME: R_0402-47K5625MW195-0599-000-195-0599-00047K; DRAWING: @P3449_B01_LIB.P3449_B01(SCH_1):PAGE4; MAX_WATTAGE: 62.5mW; NV_PN: 195-0599-000; PATH: I67; PHYS_PAGE: 4; ROT: 0; SEC: 1; SIGNAL_MODEL: nv_res; SKU: NO STUFF; TOL: 5%; VER: 2; XY: (-1150,6850)
R164 = R: ASSEMBLY: CVB_CONN; CDS_LIB: discrete; CDS_PART_NAME: R_0402-10K,5 %,62.5MW,195-0486-000; CDS_PHYS_PART_NAME: R_0402-10K,5 %,62.5MW,195-0486-000-10K,195-0486-000; CDS_SEC: 1; DEVICE_TYPENAME: R_0402-10K5625MW195-0486-000-10K195-0486-000; DRAWING: @P3449_B01_LIB.P3449_B01(SCH_1):PAGE4; MAX_WATTAGE: 62.5mW; NV_PN: 195-0486-000; PATH: I76; PHYS_PAGE: 4; ROT: 0; SEC: 1; SIGNAL_MODEL: nv_res; TOL: 5%; VER: 2; XY: (-1400,3900)
R297 = R: ASSEMBLY: POWER_LED; CDS_LIB: discrete; CDS_PART_NAME: R_0402-1.8K,5 %,62.5MW,195-0528-000; CDS_PHYS_PART_NAME: R_0402-1.8K,5 %,62.5MW,195-0528-000-1.8K,195-0528-000; CDS_SEC: 1; DEVICE_TYPENAME: R_0402-18K5625MW195-0528-000-18K195-0528-000; DRAWING: @P3449_B01_LIB.P3449_B01(SCH_1):PAGE4; MAX_WATTAGE: 62.5mW; NV_PN: 195-0528-000; PATH: I94; PHYS_PAGE: 4; ROT: 0; SEC: 1; SIGNAL_MODEL: nv_res; TOL: 5%; VER: 2; XY: (-1550,2000)
R490 = R#1: ASSEMBLY: POWER_LED; CDS_LIB: discrete; CDS_PART_NAME: R_0402-0OHM,0.05 OHM,62.5MW,195-2655-000; CDS_PHYS_PART_NAME: R_0402-0OHM,0.05 OHM,62.5MW,195-2655-000-0OHM,195-2655-000; CDS_SEC: 1; CHIPS_PART_NAME: R; DEVICE_TYPENAME: R_0402-0OHM005OHM625MW195-2655-000-0OHM195-2655-000; DRAWING: @P3449_B01_LIB.P3449_B01(SCH_1):PAGE4; MAX_WATTAGE: 62.5mW; NV_PN: 195-2655-000; PATH: I178; PHYS_PAGE: 4; ROT: 0; SEC: 1; SIGNAL_MODEL: nv_res; TOL: 0.05 ohm; VER: 1; XY: (-2500,1800)
R491 = R#1: ASSEMBLY: POWER_LED; CDS_LIB: discrete; CDS_PART_NAME: R_0402-0OHM,0.05 OHM,62.5MW,195-2655-000; CDS_PHYS_PART_NAME: R_0402-0OHM,0.05 OHM,62.5MW,195-2655-000-0OHM,195-2655-000; CDS_SEC: 1; CHIPS_PART_NAME: R; DEVICE_TYPENAME: R_0402-0OHM005OHM625MW195-2655-000-0OHM195-2655-000; DRAWING: @P3449_B01_LIB.P3449_B01(SCH_1):PAGE4; MAX_WATTAGE: 62.5mW; NV_PN: 195-2655-000; PATH: I176; PHYS_PAGE: 4; ROT: 0; SEC: 1; SIGNAL_MODEL: nv_res; SKU: NO STUFF; TOL: 0.05 ohm; VER: 1; XY: (-2500,1550)
TP1 = LABTESTPOINT#1: CDS_LIB: electro_mechanic; CDS_PART_NAME: LABTESTPOINT_PIN-LTPB071C125; CDS_PHYS_PART_NAME: LABTESTPOINT_PIN-LTPB071C125; CDS_SEC: 1; DEVICE_TYPENAME: LABTESTPOINT_PIN-LTPB071C125; DRAWING: @P3449_B01_LIB.P3449_B01(SCH_1):PAGE4; NV_NAME: LTPB071C125; PACK_TYPE: PIN; PATH: I151; PHYS_PAGE: 4; ROT: 0; SEC: 1; VER: 3; XY: (-5600,4250)
TP2 = LABTESTPOINT#1: CDS_LIB: electro_mechanic; CDS_PART_NAME: LABTESTPOINT_PIN-LTPB071C125; CDS_PHYS_PART_NAME: LABTESTPOINT_PIN-LTPB071C125; CDS_SEC: 1; DEVICE_TYPENAME: LABTESTPOINT_PIN-LTPB071C125; DRAWING: @P3449_B01_LIB.P3449_B01(SCH_1):PAGE4; NV_NAME: LTPB071C125; PACK_TYPE: PIN; PATH: I150; PHYS_PAGE: 4; ROT: 0; SEC: 1; VER: 3; XY: (-5600,4150)
R87 = R#1: ASSEMBLY: CVB_CONN; CDS_LIB: discrete; CDS_PART_NAME: R_0402-1.6K,5 %,62.5MW,195-0599-000; CDS_PHYS_PART_NAME: R_0402-1.6K,5 %,62.5MW,195-0599-000-195-0599-000,47K; CDS_SEC: 1; CHIPS_PART_NAME: R; DEVICE_TYPENAME: R_0402-47K5625MW195-0599-000-195-0599-00047K; DRAWING: @P3449_B01_LIB.P3449_B01(SCH_1):PAGE5; MAX_WATTAGE: 62.5mW; NV_PN: 195-0599-000; PATH: I186; PHYS_PAGE: 5; ROT: 0; SEC: 1; SIGNAL_MODEL: nv_res; SKU: COMMON; TOL: 5%; VER: 1; XY: (-1100,2600)
R88 = R#1: ASSEMBLY: CVB_CONN; CDS_LIB: discrete; CDS_PART_NAME: R_0402-1.6K,5 %,62.5MW,195-0599-000; CDS_PHYS_PART_NAME: R_0402-1.6K,5 %,62.5MW,195-0599-000-195-0599-000,47K; CDS_SEC: 1; CHIPS_PART_NAME: R; DEVICE_TYPENAME: R_0402-47K5625MW195-0599-000-195-0599-00047K; DRAWING: @P3449_B01_LIB.P3449_B01(SCH_1):PAGE5; MAX_WATTAGE: 62.5mW; NV_PN: 195-0599-000; PATH: I185; PHYS_PAGE: 5; ROT: 0; SEC: 1; SIGNAL_MODEL: nv_res; SKU: COMMON; TOL: 5%; VER: 1; XY: (-950,2700)
TP47 = LABTESTPOINT#1: CDS_LIB: electro_mechanic; CDS_PART_NAME: LABTESTPOINT_PIN-LTPB071C125; CDS_PHYS_PART_NAME: LABTESTPOINT_PIN-LTPB071C125; CDS_SEC: 1; DEVICE_TYPENAME: LABTESTPOINT_PIN-LTPB071C125; DRAWING: @P3449_B01_LIB.P3449_B01(SCH_1):PAGE5; NV_NAME: LTPB071C125; PACK_TYPE: PIN; PATH: I200; PHYS_PAGE: 5; ROT: 0; SEC: 1; VER: 3; XY: (-2450,5800)
TP48 = LABTESTPOINT#1: CDS_LIB: electro_mechanic; CDS_PART_NAME: LABTESTPOINT_PIN-LTPB071C125; CDS_PHYS_PART_NAME: LABTESTPOINT_PIN-LTPB071C125; CDS_SEC: 1; DEVICE_TYPENAME: LABTESTPOINT_PIN-LTPB071C125; DRAWING: @P3449_B01_LIB.P3449_B01(SCH_1):PAGE5; NV_NAME: LTPB071C125; PACK_TYPE: PIN; PATH: I202; PHYS_PAGE: 5; ROT: 0; SEC: 1; VER: 3; XY: (-2450,5900)
TP49 = LABTESTPOINT#1: CDS_LIB: electro_mechanic; CDS_PART_NAME: LABTESTPOINT_PIN-LTPB071C125; CDS_PHYS_PART_NAME: LABTESTPOINT_PIN-LTPB071C125; CDS_SEC: 1; DEVICE_TYPENAME: LABTESTPOINT_PIN-LTPB071C125; DRAWING: @P3449_B01_LIB.P3449_B01(SCH_1):PAGE5; NV_NAME: LTPB071C125; PACK_TYPE: PIN; PATH: I199; PHYS_PAGE: 5; ROT: 0; SEC: 1; VER: 3; XY: (-2450,5600)
TP50 = LABTESTPOINT#1: CDS_LIB: electro_mechanic; CDS_PART_NAME: LABTESTPOINT_PIN-LTPB071C125; CDS_PHYS_PART_NAME: LABTESTPOINT_PIN-LTPB071C125; CDS_SEC: 1; DEVICE_TYPENAME: LABTESTPOINT_PIN-LTPB071C125; DRAWING: @P3449_B01_LIB.P3449_B01(SCH_1):PAGE5; NV_NAME: LTPB071C125; PACK_TYPE: PIN; PATH: I203; PHYS_PAGE: 5; ROT: 0; SEC: 1; VER: 3; XY: (-2450,5700)
TP51 = LABTESTPOINT#1: CDS_LIB: electro_mechanic; CDS_PART_NAME: LABTESTPOINT_PIN-LTPB071C125; CDS_PHYS_PART_NAME: LABTESTPOINT_PIN-LTPB071C125; CDS_SEC: 1; DEVICE_TYPENAME: LABTESTPOINT_PIN-LTPB071C125; DRAWING: @P3449_B01_LIB.P3449_B01(SCH_1):PAGE5; NV_NAME: LTPB071C125; PACK_TYPE: PIN; PATH: I198; PHYS_PAGE: 5; ROT: 0; SEC: 1; VER: 3; XY: (-2450,5400)
TP52 = LABTESTPOINT#1: CDS_LIB: electro_mechanic; CDS_PART_NAME: LABTESTPOINT_PIN-LTPB071C125; CDS_PHYS_PART_NAME: LABTESTPOINT_PIN-LTPB071C125; CDS_SEC: 1; DEVICE_TYPENAME: LABTESTPOINT_PIN-LTPB071C125; DRAWING: @P3449_B01_LIB.P3449_B01(SCH_1):PAGE5; NV_NAME: LTPB071C125; PACK_TYPE: PIN; PATH: I201; PHYS_PAGE: 5; ROT: 0; SEC: 1; VER: 3; XY: (-2450,5500)
TP53 = LABTESTPOINT#1: CDS_LIB: electro_mechanic; CDS_PART_NAME: LABTESTPOINT_PIN-LTPB071C125; CDS_PHYS_PART_NAME: LABTESTPOINT_PIN-LTPB071C125; CDS_SEC: 1; DEVICE_TYPENAME: LABTESTPOINT_PIN-LTPB071C125; DRAWING: @P3449_B01_LIB.P3449_B01(SCH_1):PAGE5; NV_NAME: LTPB071C125; PACK_TYPE: PIN; PATH: I206; PHYS_PAGE: 5; ROT: 0; SEC: 1; VER: 3; XY: (-2450,3650)
TP54 = LABTESTPOINT#1: CDS_LIB: electro_mechanic; CDS_PART_NAME: LABTESTPOINT_PIN-LTPB071C125; CDS_PHYS_PART_NAME: LABTESTPOINT_PIN-LTPB071C125; CDS_SEC: 1; DEVICE_TYPENAME: LABTESTPOINT_PIN-LTPB071C125; DRAWING: @P3449_B01_LIB.P3449_B01(SCH_1):PAGE5; NV_NAME: LTPB071C125; PACK_TYPE: PIN; PATH: I207; PHYS_PAGE: 5; ROT: 0; SEC: 1; VER: 3; XY: (-2450,3750)
TP55 = LABTESTPOINT#1: CDS_LIB: electro_mechanic; CDS_PART_NAME: LABTESTPOINT_PIN-LTPB071C125; CDS_PHYS_PART_NAME: LABTESTPOINT_PIN-LTPB071C125; CDS_SEC: 1; DEVICE_TYPENAME: LABTESTPOINT_PIN-LTPB071C125; DRAWING: @P3449_B01_LIB.P3449_B01(SCH_1):PAGE5; NV_NAME: LTPB071C125; PACK_TYPE: PIN; PATH: I204; PHYS_PAGE: 5; ROT: 0; SEC: 1; VER: 3; XY: (-2450,3250)
TP56 = LABTESTPOINT#1: CDS_LIB: electro_mechanic; CDS_PART_NAME: LABTESTPOINT_PIN-LTPB071C125; CDS_PHYS_PART_NAME: LABTESTPOINT_PIN-LTPB071C125; CDS_SEC: 1; DEVICE_TYPENAME: LABTESTPOINT_PIN-LTPB071C125; DRAWING: @P3449_B01_LIB.P3449_B01(SCH_1):PAGE5; NV_NAME: LTPB071C125; PACK_TYPE: PIN; PATH: I208; PHYS_PAGE: 5; ROT: 0; SEC: 1; VER: 3; XY: (-2450,3350)
TP57 = LABTESTPOINT#1: CDS_LIB: electro_mechanic; CDS_PART_NAME: LABTESTPOINT_PIN-LTPB071C125; CDS_PHYS_PART_NAME: LABTESTPOINT_PIN-LTPB071C125; CDS_SEC: 1; DEVICE_TYPENAME: LABTESTPOINT_PIN-LTPB071C125; DRAWING: @P3449_B01_LIB.P3449_B01(SCH_1):PAGE5; NV_NAME: LTPB071C125; PACK_TYPE: PIN; PATH: I205; PHYS_PAGE: 5; ROT: 0; SEC: 1; VER: 3; XY: (-2450,3450)
TP58 = LABTESTPOINT#1: CDS_LIB: electro_mechanic; CDS_PART_NAME: LABTESTPOINT_PIN-LTPB071C125; CDS_PHYS_PART_NAME: LABTESTPOINT_PIN-LTPB071C125; CDS_SEC: 1; DEVICE_TYPENAME: LABTESTPOINT_PIN-LTPB071C125; DRAWING: @P3449_B01_LIB.P3449_B01(SCH_1):PAGE5; NV_NAME: LTPB071C125; PACK_TYPE: PIN; PATH: I209; PHYS_PAGE: 5; ROT: 0; SEC: 1; VER: 3; XY: (-2450,3550)
TP59 = LABTESTPOINT#1: CDS_LIB: electro_mechanic; CDS_PART_NAME: LABTESTPOINT_PIN-LTPB071C125; CDS_PHYS_PART_NAME: LABTESTPOINT_PIN-LTPB071C125; CDS_SEC: 1; DEVICE_TYPENAME: LABTESTPOINT_PIN-LTPB071C125; DRAWING: @P3449_B01_LIB.P3449_B01(SCH_1):PAGE5; NV_NAME: LTPB071C125; PACK_TYPE: PIN; PATH: I211; PHYS_PAGE: 5; ROT: 0; SEC: 1; VER: 3; XY: (-2450,3850)
TP60 = LABTESTPOINT#1: CDS_LIB: electro_mechanic; CDS_PART_NAME: LABTESTPOINT_PIN-LTPB071C125; CDS_PHYS_PART_NAME: LABTESTPOINT_PIN-LTPB071C125; CDS_SEC: 1; DEVICE_TYPENAME: LABTESTPOINT_PIN-LTPB071C125; DRAWING: @P3449_B01_LIB.P3449_B01(SCH_1):PAGE5; NV_NAME: LTPB071C125; PACK_TYPE: PIN; PATH: I212; PHYS_PAGE: 5; ROT: 0; SEC: 1; VER: 3; XY: (-2450,3950)
TP61 = LABTESTPOINT#1: CDS_LIB: electro_mechanic; CDS_PART_NAME: LABTESTPOINT_PIN-LTPB071C125; CDS_PHYS_PART_NAME: LABTESTPOINT_PIN-LTPB071C125; CDS_SEC: 1; DEVICE_TYPENAME: LABTESTPOINT_PIN-LTPB071C125; DRAWING: @P3449_B01_LIB.P3449_B01(SCH_1):PAGE5; NV_NAME: LTPB071C125; PACK_TYPE: PIN; PATH: I210; PHYS_PAGE: 5; ROT: 0; SEC: 1; VER: 3; XY: (-2450,3050)
TP62 = LABTESTPOINT#1: CDS_LIB: electro_mechanic; CDS_PART_NAME: LABTESTPOINT_PIN-LTPB071C125; CDS_PHYS_PART_NAME: LABTESTPOINT_PIN-LTPB071C125; CDS_SEC: 1; DEVICE_TYPENAME: LABTESTPOINT_PIN-LTPB071C125; DRAWING: @P3449_B01_LIB.P3449_B01(SCH_1):PAGE5; NV_NAME: LTPB071C125; PACK_TYPE: PIN; PATH: I213; PHYS_PAGE: 5; ROT: 0; SEC: 1; VER: 3; XY: (-2450,3150)
TP69 = LABTESTPOINT#1: CDS_LIB: electro_mechanic; CDS_PART_NAME: LABTESTPOINT_PIN-LTPB071C125; CDS_PHYS_PART_NAME: LABTESTPOINT_PIN-LTPB071C125; CDS_SEC: 1; DEVICE_TYPENAME: LABTESTPOINT_PIN-LTPB071C125; DRAWING: @P3449_B01_LIB.P3449_B01(SCH_1):PAGE5; NV_NAME: LTPB071C125; PACK_TYPE: PIN; PATH: I216; PHYS_PAGE: 5; ROT: 0; SEC: 1; VER: 3; XY: (-2450,4500)
TP70 = LABTESTPOINT#1: CDS_LIB: electro_mechanic; CDS_PART_NAME: LABTESTPOINT_PIN-LTPB071C125; CDS_PHYS_PART_NAME: LABTESTPOINT_PIN-LTPB071C125; CDS_SEC: 1; DEVICE_TYPENAME: LABTESTPOINT_PIN-LTPB071C125; DRAWING: @P3449_B01_LIB.P3449_B01(SCH_1):PAGE5; NV_NAME: LTPB071C125; PACK_TYPE: PIN; PATH: I217; PHYS_PAGE: 5; ROT: 0; SEC: 1; VER: 3; XY: (-2450,4600)
TP71 = LABTESTPOINT#1: CDS_LIB: electro_mechanic; CDS_PART_NAME: LABTESTPOINT_PIN-LTPB071C125; CDS_PHYS_PART_NAME: LABTESTPOINT_PIN-LTPB071C125; CDS_SEC: 1; DEVICE_TYPENAME: LABTESTPOINT_PIN-LTPB071C125; DRAWING: @P3449_B01_LIB.P3449_B01(SCH_1):PAGE5; NV_NAME: LTPB071C125; PACK_TYPE: PIN; PATH: I215; PHYS_PAGE: 5; ROT: 0; SEC: 1; VER: 3; XY: (-2450,4300)
TP72 = LABTESTPOINT#1: CDS_LIB: electro_mechanic; CDS_PART_NAME: LABTESTPOINT_PIN-LTPB071C125; CDS_PHYS_PART_NAME: LABTESTPOINT_PIN-LTPB071C125; CDS_SEC: 1; DEVICE_TYPENAME: LABTESTPOINT_PIN-LTPB071C125; DRAWING: @P3449_B01_LIB.P3449_B01(SCH_1):PAGE5; NV_NAME: LTPB071C125; PACK_TYPE: PIN; PATH: I218; PHYS_PAGE: 5; ROT: 0; SEC: 1; VER: 3; XY: (-2450,4400)
TP73 = LABTESTPOINT#1: CDS_LIB: electro_mechanic; CDS_PART_NAME: LABTESTPOINT_PIN-LTPB071C125; CDS_PHYS_PART_NAME: LABTESTPOINT_PIN-LTPB071C125; CDS_SEC: 1; DEVICE_TYPENAME: LABTESTPOINT_PIN-LTPB071C125; DRAWING: @P3449_B01_LIB.P3449_B01(SCH_1):PAGE5; NV_NAME: LTPB071C125; PACK_TYPE: PIN; PATH: I214; PHYS_PAGE: 5; ROT: 0; SEC: 1; VER: 3; XY: (-2450,4100)
TP74 = LABTESTPOINT#1: CDS_LIB: electro_mechanic; CDS_PART_NAME: LABTESTPOINT_PIN-LTPB071C125; CDS_PHYS_PART_NAME: LABTESTPOINT_PIN-LTPB071C125; CDS_SEC: 1; DEVICE_TYPENAME: LABTESTPOINT_PIN-LTPB071C125; DRAWING: @P3449_B01_LIB.P3449_B01(SCH_1):PAGE5; NV_NAME: LTPB071C125; PACK_TYPE: PIN; PATH: I219; PHYS_PAGE: 5; ROT: 0; SEC: 1; VER: 3; XY: (-2450,4200)
TP110 = LABTESTPOINT: CDS_LIB: electro_mechanic; CDS_PART_NAME: LABTESTPOINT_PIN-LTPB071C125; CDS_PHYS_PART_NAME: LABTESTPOINT_PIN-LTPB071C125; CDS_SEC: 1; DEVICE_TYPENAME: LABTESTPOINT_PIN-LTPB071C125; DRAWING: @P3449_B01_LIB.P3449_B01(SCH_1):PAGE5; NV_NAME: LTPB071C125; PACK_TYPE: PIN; PATH: I247; PHYS_PAGE: 5; ROT: 0; SEC: 1; VER: 1; XY: (-10450,3450)
TP111 = LABTESTPOINT: CDS_LIB: electro_mechanic; CDS_PART_NAME: LABTESTPOINT_PIN-LTPB071C125; CDS_PHYS_PART_NAME: LABTESTPOINT_PIN-LTPB071C125; CDS_SEC: 1; DEVICE_TYPENAME: LABTESTPOINT_PIN-LTPB071C125; DRAWING: @P3449_B01_LIB.P3449_B01(SCH_1):PAGE5; NV_NAME: LTPB071C125; PACK_TYPE: PIN; PATH: I248; PHYS_PAGE: 5; ROT: 0; SEC: 1; VER: 1; XY: (-10450,3350)
TP112 = LABTESTPOINT: CDS_LIB: electro_mechanic; CDS_PART_NAME: LABTESTPOINT_PIN-LTPB071C125; CDS_PHYS_PART_NAME: LABTESTPOINT_PIN-LTPB071C125; CDS_SEC: 1; DEVICE_TYPENAME: LABTESTPOINT_PIN-LTPB071C125; DRAWING: @P3449_B01_LIB.P3449_B01(SCH_1):PAGE5; NV_NAME: LTPB071C125; PACK_TYPE: PIN; PATH: I249; PHYS_PAGE: 5; ROT: 0; SEC: 1; VER: 1; XY: (-10450,3250)
TP113 = LABTESTPOINT: CDS_LIB: electro_mechanic; CDS_PART_NAME: LABTESTPOINT_PIN-LTPB071C125; CDS_PHYS_PART_NAME: LABTESTPOINT_PIN-LTPB071C125; CDS_SEC: 1; DEVICE_TYPENAME: LABTESTPOINT_PIN-LTPB071C125; DRAWING: @P3449_B01_LIB.P3449_B01(SCH_1):PAGE5; NV_NAME: LTPB071C125; PACK_TYPE: PIN; PATH: I250; PHYS_PAGE: 5; ROT: 0; SEC: 1; VER: 1; XY: (-10450,3150)
TP114 = LABTESTPOINT: CDS_LIB: electro_mechanic; CDS_PART_NAME: LABTESTPOINT_PIN-LTPB071C125; CDS_PHYS_PART_NAME: LABTESTPOINT_PIN-LTPB071C125; CDS_SEC: 1; DEVICE_TYPENAME: LABTESTPOINT_PIN-LTPB071C125; DRAWING: @P3449_B01_LIB.P3449_B01(SCH_1):PAGE5; NV_NAME: LTPB071C125; PACK_TYPE: PIN; PATH: I251; PHYS_PAGE: 5; ROT: 0; SEC: 1; VER: 1; XY: (-10450,3050)
TP115 = LABTESTPOINT: CDS_LIB: electro_mechanic; CDS_PART_NAME: LABTESTPOINT_PIN-LTPB071C125; CDS_PHYS_PART_NAME: LABTESTPOINT_PIN-LTPB071C125; CDS_SEC: 1; DEVICE_TYPENAME: LABTESTPOINT_PIN-LTPB071C125; DRAWING: @P3449_B01_LIB.P3449_B01(SCH_1):PAGE5; NV_NAME: LTPB071C125; PACK_TYPE: PIN; PATH: I252; PHYS_PAGE: 5; ROT: 0; SEC: 1; VER: 1; XY: (-10450,2950)
TP120-TP127 = LABTESTPOINT#1: CDS_LIB: electro_mechanic; CDS_LOCATION: TP51; CDS_PART_NAME: LABTESTPOINT_PIN-LTPB071C125; CDS_PHYS_PART_NAME: LABTESTPOINT_PIN-LTPB071C125; CDS_SEC: 1; DEVICE_TYPENAME: LABTESTPOINT_PIN-LTPB071C125; DRAWING: @P3449_B01_LIB.P3449_B01(SCH_1):PAGE5; LOCATION: TP51; NV_NAME: LTPB071C125; PACK_TYPE: PIN; PATH: I198; PHYS_PAGE: 5; ROT: 0; SEC: 1; VER: 3; XY: (-2450,5400)
J2 = CON_SODIMM_260: ANGLE: 90; ASSEMBLY: CVB_CONN; CDS_LIB: p3449_b01_lib; CDS_PART_NAME: CON_SODIMM_260_CON_SODIMM260_JETSON_NANO-2309413-1,FEMALE,0.5MM,90,[ ],[ ],YES,NO,NO,25 V,0.5 A,080-1656-000; CDS_PHYS_PART_NAME: CON_SODIMM_260_CON_SODIMM260_JETSON_NANO-2309413-1,FEMALE,0.5MM,90,[ ],[ ],YES,NO,NO,25 V,0.5 A,080-1656-000-080-1656-000; CDS_SEC: 1; CaptureCellPackProp: CON_SODIMM_260A; DEVICE_TYPENAME: CON_SODIMM_260_CON_SODIMM260_JETSON_NANO-2309413-1FEMALE05MM90YESNONO25V05A080-1656-000-080-1656-000; DRAWING: @P3449_B01_LIB.P3449_B01(SCH_1):PAGE4; EMI_GROUND_TAB: NO; GENDER: FEMALE; LATCHING: YES; MAX_CURRENT: 0.5 A; MAX_VOLTAGE: 25 V; NV_NAME: 2309413-1; NV_PN: 080-1656-000; PACK_TYPE: CON_SODIMM260_JETSON_NANO; PATH: I79; PHYS_PAGE: 4; PITCH: 0.5mm; REFLOW: [ ]; ROT: 0; SEC: 1; SEC_TYPE: CON_SODIMM260_JETSON_NANO; SHIELDED: NO; SHROUDED: [ ]; VER: 5; XY: (-9250,3800)
MEC6 = MOUNTING_HOLE: CDS_LIB: mechanic; CDS_PART_NAME: MOUNTING_HOLE_X2-P3449_MOUNTING_HOLE; CDS_PHYS_PART_NAME: MOUNTING_HOLE_X2-P3449_MOUNTING_HOLE; CDS_SEC: 1; DEVICE_TYPENAME: MOUNTING_HOLE_X2-P3449_MOUNTING_HOLE; DRAWING: @P3449_B01_LIB.P3449_B01(SCH_1):PAGE22; NV_NAME: P3449_MOUNTING_HOLE; PACK_TYPE: X2; PATH: I1; PHYS_PAGE: 22; ROT: 0; SEC: 1; VER: 1; XY: (-9550,4550)

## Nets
GND: C5.2 C250.2 C309.2 C342.2 D41.2 D42.2 D43.2 J2.1(GND1) J2.2(GND2) J2.7(GND3) J2.8(GND4) J2.13(GND5) J2.14(GND6) J2.19(GND7) J2.20(GND8) J2.25(GND9) J2.26(GND10) J2.31(GND11) J2.32(GND12) J2.37(GND13) J2.38(GND14) J2.43(GND15) J2.44(GND16) J2.49(GND17) J2.50(GND18) J2.55(GND19) J2.56(GND20) J2.61(GND21) J2.62(GND22) J2.67(GND23) J2.68(GND24) J2.73(GND25) J2.74(GND26) J2.79(GND27) J2.80(GND28) J2.85(GND29) J2.86(GND30) J2.102(GND31) J2.107(GND32) J2.113(GND33) J2.119(GND34) J2.125(GND35) J2.129(GND36) J2.132(GND37) J2.135(GND38) J2.138(GND39) J2.141(GND40) J2.144(GND41) J2.146(GND42) J2.147(GND43) J2.152(GND44) J2.153(GND45) J2.158(GND46) J2.159(GND47) J2.164(GND48) J2.165(GND49) J2.170(GND50) J2.171(GND51) J2.176(GND52) J2.177(GND53) J2.200(GND54) J2.201(GND55) J2.217(GND56) J2.231(GND57) J2.241(GND58) J2.242(GND59) J2.243(GND60) J2.244(GND61) J2.245(GND62) J2.246(GND63) J2.247(GND64) J2.248(GND65) J2.249(GND66) J2.250(GND67) J2.261(MNT1) J2.262(MNT2) J45.2 MEC6.1(GND) MEC6.2(GND) Q43.2(S) ; also on sheet 2 3 4 5 6 7 8 9 10 11 12 13 14 15
VDD_1V8: R65.1 R66.1 ; also on sheet 2 3 5 6 8 10
VDD_3V3_SYS: R63.1 R64.1 R67.1 R68.1 R87.1 R88.1 ; also on sheet 2 3 4 5 6 7 8 10
VDD_5V_IN: C250.1 C309.1 C342.1 DS3.2(A) J2.251(VDD_IN1) J2.252(VDD_IN2) J2.253(VDD_IN3) J2.254(VDD_IN4) J2.255(VDD_IN5) J2.256(VDD_IN6) J2.257(VDD_IN7) J2.258(VDD_IN8) J2.259(VDD_IN9) J2.260(VDD_IN10) R164.1 ; also on sheet 2 3 6 9 10 11 13 14
BBAT: C5.1 D64.1(C) J2.235(PMIC_BBAT)
BBAT_CONN: D64.2(A) J45.1 J45.3
BT_M2_EN: J2.126(GPS_EN) ; also on sheet 8
BT_M2_WAKE_AP: J2.124(GPIO_PH6) ; also on sheet 8
CAM0_MCLK: J2.116(CAM1_MCLK) ; also on sheet 4
CAM0_PWDN: J2.114(CAM1_PWDN) ; also on sheet 4
CAM1_MCLK: J2.122(CAM2_MCLK) TP126.1
CAM1_PWDN: J2.120(CAM2_PWDN) TP127.1
CAM_I2C_SCL: J2.213(CAM_I2C_SCL) R87.2 ; also on sheet 4 14
CAM_I2C_SDA: J2.215(CAM_I2C_SDA) R88.2 ; also on sheet 4 14
CAM_MUX_SEL: J2.130(NFC_EN) ; also on sheet 4
CAN_RX: J2.143(CAN_RX) TP1.1
CAN_TX: J2.145(CAN_TX) TP2.1
CSI0_CLK_N: J2.10(CSI_A_CLK_N) ; also on sheet 4
CSI0_CLK_P: J2.12(CSI_A_CLK_P) ; also on sheet 4
CSI0_D0_N: J2.4(CSI_A_D0_N) ; also on sheet 4
CSI0_D0_P: J2.6(CSI_A_D0_P) ; also on sheet 4
CSI0_D1_N: J2.16(CSI_A_D1_N) ; also on sheet 4
CSI0_D1_P: J2.18(CSI_A_D1_P) ; also on sheet 4
CSI1_CLK_N: J2.9(CSI_B_CLK_N) TP51.1
CSI1_CLK_P: J2.11(CSI_B_CLK_P) TP52.1
CSI1_D0_N: J2.3(CSI_B_D0_N) TP47.1
CSI1_D0_P: J2.5(CSI_B_D0_P) TP48.1
CSI1_D1_N: J2.15(CSI_B_D1_N) TP49.1
CSI1_D1_P: J2.17(CSI_B_D1_P) TP50.1
CSI2_CLK_N: J2.28(CSI_E_CLK_N) TP125.1
CSI2_CLK_P: J2.30(CSI_E_CLK_P) TP124.1
CSI2_D0_N: J2.22(CSI_E_D0_N) TP121.1
CSI2_D0_P: J2.24(CSI_E_D0_P) TP120.1
CSI2_D1_N: J2.34(CSI_E_D1_N) TP123.1
CSI2_D1_P: J2.36(CSI_E_D1_P) TP122.1
CSI3_CLK_N: J2.27(CSI_F_CLK_N) TP73.1
CSI3_CLK_P: J2.29(CSI_F_CLK_P) TP74.1
CSI3_D0_N: J2.21(CSI_F_D0_N) TP69.1
CSI3_D0_P: J2.23(CSI_F_D0_P) TP70.1
CSI3_D1_N: J2.33(CSI_F_D1_N) TP71.1
CSI3_D1_P: J2.35(CSI_F_D1_P) TP72.1
CSI4_CLK_N: J2.52(CSI_C_CLK_N) TP57.1
CSI4_CLK_P: J2.54(CSI_C_CLK_P) TP58.1
CSI4_D0_N: J2.46(CSI_C_D0_N) TP53.1
CSI4_D0_P: J2.48(CSI_C_D0_P) TP54.1
CSI4_D1_N: J2.58(CSI_C_D1_N) TP55.1
CSI4_D1_P: J2.60(CSI_C_D1_P) TP56.1
CSI4_D2_N: J2.40(CSI_D_D0_N) TP59.1
CSI4_D2_P: J2.42(CSI_D_D0_P) TP60.1
CSI4_D3_N: J2.64(CSI_D_D1_N) TP61.1
CSI4_D3_P: J2.66(CSI_D_D1_P) TP62.1
FAN_PWM: J2.230(GPIO_PE7) ; also on sheet 2
FAN_TACH: J2.208(GPIO_PZ2) ; also on sheet 2
FORCE_OFF*: J2.233(SHUTDOWN_REQ*) ; also on sheet 9
FORCE_RECOVERY*: D42.1 J2.214(FORCE_RECOVERY*) ; also on sheet 2
GBE_LED_ACT: J2.194(GBE_LED1) ; also on sheet 7
GBE_LED_LINK: J2.188(GBE_LED0) ; also on sheet 7
GBE_MDI0_N: J2.184(GBE_MDI0_N) ; also on sheet 7
GBE_MDI0_P: J2.186(GBE_MDI0_P) ; also on sheet 7
GBE_MDI1_N: J2.190(GBE_MDI1_N) ; also on sheet 7
GBE_MDI1_P: J2.192(GBE_MDI1_P) ; also on sheet 7
GBE_MDI2_N: J2.196(GBE_MDI2_N) ; also on sheet 7
GBE_MDI2_P: J2.198(GBE_MDI2_P) ; also on sheet 7
GBE_MDI3_N: J2.202(GBE_MDI3_N) ; also on sheet 7
GBE_MDI3_P: J2.204(GBE_MDI3_P) ; also on sheet 7
GPIO01: J2.118(CAM_AF_EN) ; also on sheet 3
GPIO07: J2.206(LCD_BL_PWM) ; also on sheet 3
GPIO09: J2.211(AUD_MCLK) ; also on sheet 3
GPIO11: J2.216(GPIO_PZ0) ; also on sheet 3
GPIO12: J2.218(LCD_TE) ; also on sheet 3
GPIO13: J2.228(GPIO_PE6) ; also on sheet 3
I2C1_SCL: J2.189(GEN2_I2C_SCL) R67.2 ; also on sheet 3
I2C1_SDA: J2.191(GEN2_I2C_SDA) R68.2 ; also on sheet 3
I2C2_SCL: J2.232(GEN3_I2C_SCL) R66.2 ; also on sheet 2 8
I2C2_SDA: J2.234(GEN3_I2C_SDA) R65.2 ; also on sheet 2 8
I2S0_LRCK: J2.197(DAP4_FS) ; also on sheet 3
I2S0_SCLK: J2.199(DAP4_SCLK) ; also on sheet 3
I2S0_SDIN: J2.195(DAP4_DIN) ; also on sheet 3
I2S0_SDOUT: J2.193(DAP4_DOUT) ; also on sheet 3
I2S1_LRCK: J2.224(DAP3_FS) ; also on sheet 8
I2S1_SCLK: J2.226(DAP3_SCLK) ; also on sheet 8
I2S1_SDIN: J2.222(DAP3_DIN) ; also on sheet 8
I2S1_SDOUT: J2.220(DAP3_DOUT) ; also on sheet 8
ID_I2C_SCL: J2.185(GEN1_I2C_SCL) R63.2 ; also on sheet 3
ID_I2C_SDA: J2.187(GEN1_I2C_SDA) R64.2 ; also on sheet 3
LED0_CTRL: Q43.1(G) R490.2 R491.2
M2_E_ALERT: J2.212(LCD_BL_EN) ; also on sheet 8
MOD_SLEEP*: J2.178(GPIO_PA6) R491.1 ; also on sheet 2 6
POWER_EN: J2.237(POWER_EN) ; also on sheet 9
PWR_BTN*: D43.1 J2.240(BUTTON_PWR_ON*) R164.2 ; also on sheet 2 9
PWR_LED: DS3.1(C) R297.1
PWR_LED_CTRL: J2.127(NFC_INT) R490.1 ; also on sheet 2
PWR_LED_R: Q43.3(D) R297.2
SDIO_CLK: J2.229(SDMMC3_CLK) TP115.1
SDIO_CMD: J2.227(SDMMC3_CMD) TP114.1
SDIO_D0: J2.219(SDMMC3_DAT0) TP110.1
SDIO_D1: J2.221(SDMMC3_DAT1) TP111.1
SDIO_D2: J2.223(SDMMC3_DAT2) TP112.1
SDIO_D3: J2.225(SDMMC3_DAT3) TP113.1
SPI0_CS0: J2.95(SPI1_CS0) ; also on sheet 3
SPI0_CS1: J2.97(SPI1_CS1) ; also on sheet 3
SPI0_MISO: J2.93(SPI1_MISO) ; also on sheet 3
SPI0_MOSI: J2.89(SPI1_MOSI) ; also on sheet 3
SPI0_SCK: J2.91(SPI1_SCK) ; also on sheet 3
SPI1_CS0: J2.110(SPI2_CS0) ; also on sheet 3
SPI1_CS1: J2.112(SPI2_CS1) ; also on sheet 3
SPI1_MISO: J2.108(SPI2_MISO) ; also on sheet 3
SPI1_MOSI: J2.104(SPI2_MOSI) ; also on sheet 3
SPI1_SCK: J2.106(SPI2_SCK) ; also on sheet 3
SYS_RST*: D41.1 J2.239(SYS_RESET_IN*) ; also on sheet 2 10
UART0_CTS: J2.105(UART3_CTS) ; also on sheet 8
UART0_RTS: J2.103(UART3_RTS) ; also on sheet 8
UART0_RXD: J2.101(UART3_RXD) ; also on sheet 8
UART0_TXD: J2.99(UART3_TXD) ; also on sheet 8
UART1_CTS: J2.209(UART2_CTS) ; also on sheet 3
UART1_RTS: J2.207(UART2_RTS) ; also on sheet 3
UART1_RXD: J2.205(UART2_RXD) ; also on sheet 3
UART1_TXD: J2.203(UART2_TXD) ; also on sheet 3
UART2_RXD: J2.238(UART1_RXD) ; also on sheet 2
UART2_TXD: J2.236(UART1_TXD) ; also on sheet 2
USB0_AP_N: J2.109(USB0_DN) ; also on sheet 15
USB0_AP_P: J2.111(USB0_DP) ; also on sheet 15
USB0_VBUS_DET*: J2.87(USB_VBUS_EN0) ; also on sheet 15
USB1_AP_N: J2.115(USB1_DN) ; also on sheet 14
USB1_AP_P: J2.117(USB1_DP) ; also on sheet 14
USB2_AP_N: J2.121(USB2_DN) ; also on sheet 8
USB2_AP_P: J2.123(USB2_DP) ; also on sheet 8
W_DISABLE1_CTRL: J2.128(AP_WAKE_NFC) ; also on sheet 8

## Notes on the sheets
sheet 17
- A
- B
- C
- D
- E
- F
- G
- H
- GPIOs, USB2.0, I2S, SPI, GBe and CSI
- 1
- 1
- uUSB Con
- CAM FPC Con
- USB Type-A Con
- M.2 BT
- 40Pin GPIO HDR
- PUT TESTPOINT
- 2
- ON BOTTOM OF
- 2
- PCB
- M.2 BT
- ETHERNET CON
- PUT TESTPOINT
- ON BOTTOM OF
- 3
- PCB
- 3
- PUT TESTPOINT
- ON BOTTOM OF
- PCB
- CAM FPC Con
- 4
- USB3.1 HUB
- 4
- 40Pin GPIO HDR
- 5
- 5
- NVIDIA CORPORATION
- 2701 SAN TOMAS
  EXPRESSWAY
- ASSEMBLY
- Jetson Nano Carrier Board
- SANTA CLARA, CA 95050, USA
- PAGE DETAIL
- SODIMM connector 2/3
- NV_PN
- ALL NVIDIA DESIGN SPECIFICATIONS, REFERENCE SPECIFICATIONS, REFERENCE BOARDS, FILES, DRAWINGS, DIAGNOSTICS, LISTS AND OTHER DOCUMENTS OR INFORMATION (TOGETHER AND SEPARATELY, 'MATERIALS') ARE BEING PROVIDED 'AS IS'. THE MATERIALS
  MAY
- CONTAIN KNOWN AND UNKNOWN VIOLATIONS OR DEVIATIONS OF INDUSTRY STANDARDS AND SPECIFICATIONS. NVIDIA MAKES NO WARRANTIES, EXPRESSED, IMPLIED, STATUTORY OR OTHERWISE WITH RESPECT TO THE MATERIALS OR OTHERWISE, AND EXPRESSLY DISCLAIMS
  ALL
- PCB REV
- PAGE
- 5 OF 23
- IMPLIED WARRANTIES INCLUDING, WITHOUT LIMITATION, THE WARRANTIES OF DESIGN, OF NONINFRINGEMENT, MERCHANTABILITY OR FITNESS FOR A PARTICULAR PURPOSE, OR ARISING FROM A COURSE OF DEALING, TRADE USAGE, TRADE PRACTICE, OR INDUSTRY
  STANDARDS.
- BOM REV
- A
- DATE
- 08-MAY-2019
- A
- B
- C
- D
- E
- F
- G
- H
sheet 18
- A
- B
- C
- D
- E
- F
- G
- H
- UART, I2C, CAN and GPIOs
- I2C PULL-UP
- 1
- NO STUFF THESE
- 1
- M.2 WIFI/BT
- 2
- 2
- 40PIN GPIO EXPANSION HEADER
- DEBUG
- PULL-UP FOR POWER BUTTON
- USE EITHER SUPERCAP OR COIN CELL BATTERY
- 3
- 3
- PLACE J45 ON BACK
- OF PCB
- COIN CELL: CR1225
- POWER LED
- 4
- 4
- 5
- 5
- NVIDIA CORPORATION
- 2701 SAN TOMAS
  EXPRESSWAY
- ASSEMBLY
- Jetson Nano Carrier Board
- SANTA CLARA, CA 95050, USA
- PAGE DETAIL
- SODIMM connector 1/3
- NV_PN
- ALL NVIDIA DESIGN SPECIFICATIONS, REFERENCE SPECIFICATIONS, REFERENCE BOARDS, FILES, DRAWINGS, DIAGNOSTICS, LISTS AND OTHER DOCUMENTS OR INFORMATION (TOGETHER AND SEPARATELY, 'MATERIALS') ARE BEING PROVIDED 'AS IS'. THE MATERIALS
  MAY
- CONTAIN KNOWN AND UNKNOWN VIOLATIONS OR DEVIATIONS OF INDUSTRY STANDARDS AND SPECIFICATIONS. NVIDIA MAKES NO WARRANTIES, EXPRESSED, IMPLIED, STATUTORY OR OTHERWISE WITH RESPECT TO THE MATERIALS OR OTHERWISE, AND EXPRESSLY DISCLAIMS
  ALL
- PCB REV
- PAGE
- 4 OF 23
- IMPLIED WARRANTIES INCLUDING, WITHOUT LIMITATION, THE WARRANTIES OF DESIGN, OF NONINFRINGEMENT, MERCHANTABILITY OR FITNESS FOR A PARTICULAR PURPOSE, OR ARISING FROM A COURSE OF DEALING, TRADE USAGE, TRADE PRACTICE, OR INDUSTRY
  STANDARDS.
- BOM REV
- A
- DATE
- 08-MAY-2019
- A
- B
- C
- D
- E
- F
- G
- H
sheet 19
- A
- B
- C
- D
- E
- F
- G
- H
- Power Tree
- 1
- 1
- 2
- 2
- 3
- 3
- 4
- 4
- 5
- 5
- NVIDIA CORPORATION
- 2701 SAN TOMAS
  EXPRESSWAY
- ASSEMBLY
- Jetson Nano Carrier Board
- SANTA CLARA, CA 95050, USA
- PAGE DETAIL
- Power
  Tree
- NV_PN
- ALL NVIDIA DESIGN SPECIFICATIONS, REFERENCE SPECIFICATIONS, REFERENCE BOARDS, FILES, DRAWINGS, DIAGNOSTICS, LISTS AND OTHER DOCUMENTS OR INFORMATION (TOGETHER AND SEPARATELY, 'MATERIALS') ARE BEING PROVIDED 'AS IS'. THE MATERIALS
  MAY
- CONTAIN KNOWN AND UNKNOWN VIOLATIONS OR DEVIATIONS OF INDUSTRY STANDARDS AND SPECIFICATIONS. NVIDIA MAKES NO WARRANTIES, EXPRESSED, IMPLIED, STATUTORY OR OTHERWISE WITH RESPECT TO THE MATERIALS OR OTHERWISE, AND EXPRESSLY DISCLAIMS
  ALL
- PCB REV
- PAGE
- 3 OF 23
- .
- IMPLIED WARRANTIES INCLUDING, WITHOUT LIMITATION, THE WARRANTIES OF DESIGN, OF NONINFRINGEMENT, MERCHANTABILITY OR FITNESS FOR A PARTICULAR PURPOSE, OR ARISING FROM A COURSE OF DEALING, TRADE USAGE, TRADE PRACTICE, OR INDUSTRY
  STANDARDS.
- BOM REV
- A
- DATE
- 08-MAY-2019
- A
- B
- C
- D
- E
- F
- G
- H
sheet 20
- A
- B
- C
- D
- E
- F
- G
- H
- Blank Page
- 1
- 1
- 2
- 2
- 3
- 3
- 4
- 4
- 5
- 5
- NVIDIA CORPORATION
- 2701 SAN TOMAS
  EXPRESSWAY
- ASSEMBLY
- Jetson Nano Carrier Board
- SANTA CLARA, CA 95050, USA
- PAGE DETAIL
- Block
  Diagram
- NV_PN
- ALL NVIDIA DESIGN SPECIFICATIONS, REFERENCE SPECIFICATIONS, REFERENCE BOARDS, FILES, DRAWINGS, DIAGNOSTICS, LISTS AND OTHER DOCUMENTS OR INFORMATION (TOGETHER AND SEPARATELY, 'MATERIALS') ARE BEING PROVIDED 'AS IS'. THE MATERIALS
  MAY
- CONTAIN KNOWN AND UNKNOWN VIOLATIONS OR DEVIATIONS OF INDUSTRY STANDARDS AND SPECIFICATIONS. NVIDIA MAKES NO WARRANTIES, EXPRESSED, IMPLIED, STATUTORY OR OTHERWISE WITH RESPECT TO THE MATERIALS OR OTHERWISE, AND EXPRESSLY DISCLAIMS
  ALL
- PCB REV
- PAGE
- 2 OF 23
- .
- IMPLIED WARRANTIES INCLUDING, WITHOUT LIMITATION, THE WARRANTIES OF DESIGN, OF NONINFRINGEMENT, MERCHANTABILITY OR FITNESS FOR A PARTICULAR PURPOSE, OR ARISING FROM A COURSE OF DEALING, TRADE USAGE, TRADE PRACTICE, OR INDUSTRY
  STANDARDS.
- BOM REV
- A
- DATE
- 08-MAY-2019
- A
- B
- C
- D
- E
- F
- G
- H
sheet 21
- A
- B
- C
- D
- E
- F
- G
- H
- Jetson Nano Carrier Board Reference Design
- HDMI, USB, M.2, Gbe
- 1
- 1
- TABLE OF CONTENTS
- Page
- Description
- Page
- Description
- 1
- Table of Contents
- 2
- Blank Page
- 3
- Power Tree
- 4
- SODIMM connector 1/3
- 5
- SODIMM connector 2/3
- 2
- 2
- 6
- SODIMM connector 3/3
- 7
- USB2.0 micro
- 8
- USB3.1 x4 HUB
- 9
- USB3.1 Type-A x2 (A)
- 10
- USB3.1 Type-A x2 (B)
- 11
- DC Jack
- 12
- 3V3 DCDC and 1V8 LDO
- 13
- Power ON/OFF Logic
- 14
- M.2 Key-E
- 15
- Gigabit Ethernet POE
- 3
- 3
- 16
- HDMI
- 17
- DisplayPort
- 18
- CAM Connector
- 19
- 40Pin GPIO expansion header
- 20
- Fan, Debug and EEPROM
- 21
- Loop Back Test
- 22
- Mechanical
- I2C Port Assignments
- 4
- Slave Device                BUS:Device address
- 4
- BOARDID EEPROM              I2C2 : 7'57h
- RTS5411S USB3.1 HUB         CAM I2C   : 7'6Ah
- M.2 KEY-E WIFI/BT           I2C2 : TBD
- 5
- 5
- NVIDIA CORPORATION
- 2701 SAN TOMAS
  EXPRESSWAY
- ASSEMBLY
- Jetson Nano Carrier Board
- SANTA CLARA, CA 95050, USA
- PAGE DETAIL
- Table of Contents
- NV_PN
- ALL NVIDIA DESIGN SPECIFICATIONS, REFERENCE SPECIFICATIONS, REFERENCE BOARDS, FILES, DRAWINGS, DIAGNOSTICS, LISTS AND OTHER DOCUMENTS OR INFORMATION (TOGETHER AND SEPARATELY, 'MATERIALS') ARE BEING PROVIDED 'AS IS'. THE MATERIALS
  MAY
- CONTAIN KNOWN AND UNKNOWN VIOLATIONS OR DEVIATIONS OF INDUSTRY STANDARDS AND SPECIFICATIONS. NVIDIA MAKES NO WARRANTIES, EXPRESSED, IMPLIED, STATUTORY OR OTHERWISE WITH RESPECT TO THE MATERIALS OR OTHERWISE, AND EXPRESSLY DISCLAIMS
  ALL
- PCB REV
- PAGE
- 1 OF 23
- IMPLIED WARRANTIES INCLUDING, WITHOUT LIMITATION, THE WARRANTIES OF DESIGN, OF NONINFRINGEMENT, MERCHANTABILITY OR FITNESS FOR A PARTICULAR PURPOSE, OR ARISING FROM A COURSE OF DEALING, TRADE USAGE, TRADE PRACTICE, OR INDUSTRY
  STANDARDS.
- BOM REV
- A
- DATE
- 08-MAY-2019
- A
- B
- C
- D
- E
- F
- G
- H
sheet 22
- A
- B
- C
- D
- E
- F
- G
- H
- Mechanical
- 1
- 1
- 2
- 2
- Mounting holes for Module
- 3
- 3
- 4
- 4
- 5
- 5
- NVIDIA CORPORATION
- 2701 SAN TOMAS
  EXPRESSWAY
- ASSEMBLY
- Jetson Nano Carrier Board
- SANTA CLARA, CA 95050, USA
- PAGE DETAIL
- Mechanical
- NV_PN
- ALL NVIDIA DESIGN SPECIFICATIONS, REFERENCE SPECIFICATIONS, REFERENCE BOARDS, FILES, DRAWINGS, DIAGNOSTICS, LISTS AND OTHER DOCUMENTS OR INFORMATION (TOGETHER AND SEPARATELY, 'MATERIALS') ARE BEING PROVIDED 'AS IS'. THE MATERIALS
  MAY
- CONTAIN KNOWN AND UNKNOWN VIOLATIONS OR DEVIATIONS OF INDUSTRY STANDARDS AND SPECIFICATIONS. NVIDIA MAKES NO WARRANTIES, EXPRESSED, IMPLIED, STATUTORY OR OTHERWISE WITH RESPECT TO THE MATERIALS OR OTHERWISE, AND EXPRESSLY DISCLAIMS
  ALL
- PCB REV
- PAGE
- 22 OF 23
- IMPLIED WARRANTIES INCLUDING, WITHOUT LIMITATION, THE WARRANTIES OF DESIGN, OF NONINFRINGEMENT, MERCHANTABILITY OR FITNESS FOR A PARTICULAR PURPOSE, OR ARISING FROM A COURSE OF DEALING, TRADE USAGE, TRADE PRACTICE, OR INDUSTRY
  STANDARDS.
- BOM REV
- A
- DATE
- 08-MAY-2019
- A
- B
- C
- D
- E
- F
- G
- H
